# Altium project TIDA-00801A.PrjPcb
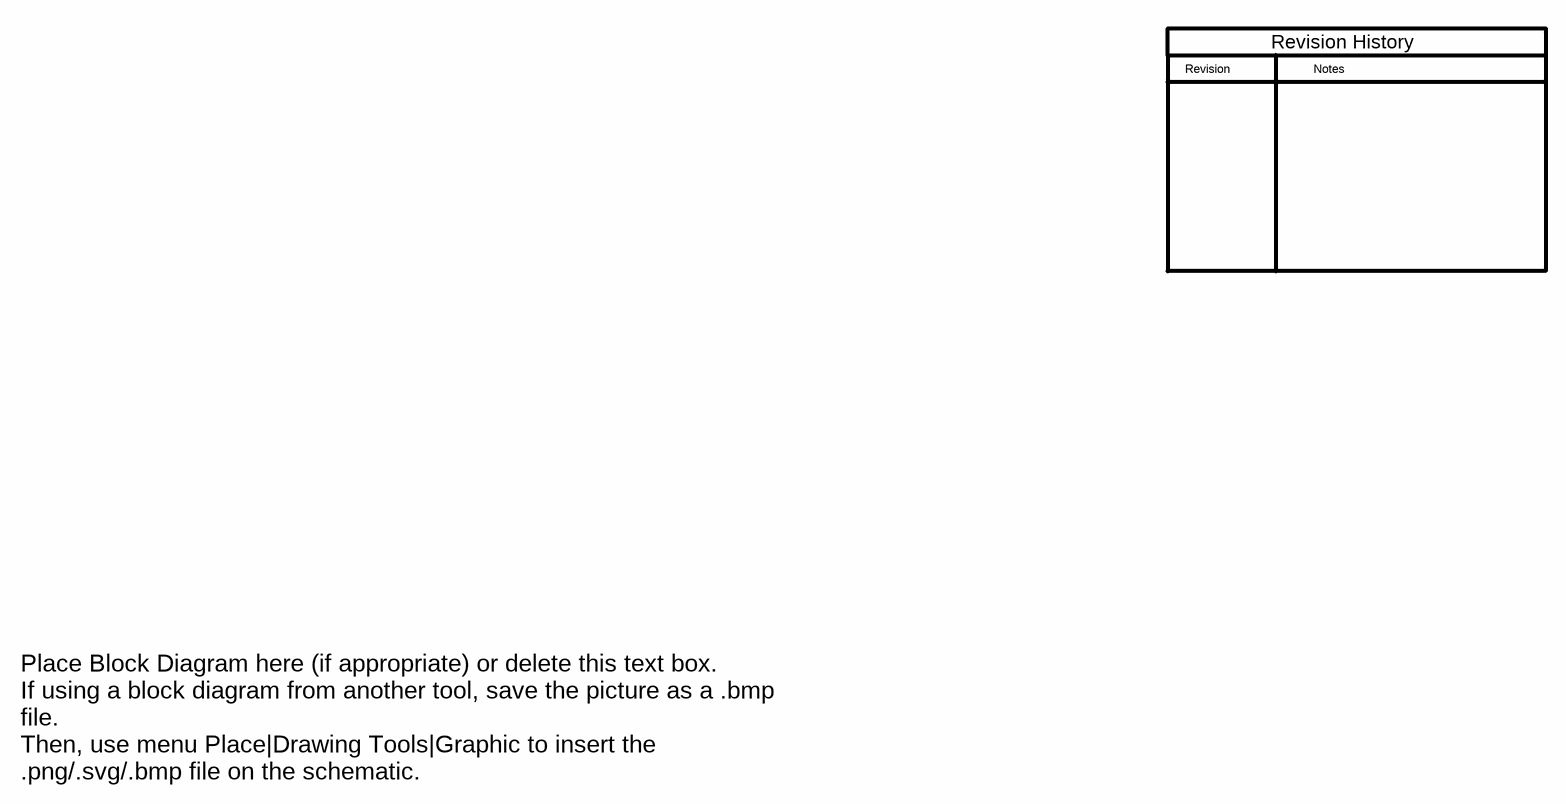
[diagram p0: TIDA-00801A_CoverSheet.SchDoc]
TID: TIDA-00801; TechSupport: http://www.ti.com/support; SCH_Rev: A; PRJ_Title: Infotainment-Power; PRJ_Number: TIDA-00801; PRJ_Engineer: Frank Dehmelt; PRJ_Customer: Public Release; PCB_Rev: A; PCB_Layout: Krypton Solutions/RS; CopyrightYear: 2015
6 sheets, 198 parts. Net scope: global (net labels, ports and power ports of the same name join across sheets).
Board file: TIDA-00801A.PcbDoc
Sheets:
  TIDA-00801A_CoverSheet.SchDoc
  TIDA-00801A_O9039A360.schdoc
  TIDA-00801A_TPS22965.schdoc
  TIDA-00801A_TPS43330.schdoc
  TIDA-00801A_TPS51200.schdoc
  TIDA-00801A_Hardware.SchDoc

## Sheet TIDA-00801A_CoverSheet.SchDoc
size 431 x 279 mm; Date: Not shown in title block; ApprovedBy: Not shown in title block; CheckedBy: Not shown in title block; Author: Not shown in title block; CompanyName: Not shown in title block; Engineer: Not shown in title block; Organization: Not shown in title block; Address1: Not shown in title block; Address2: Not shown in title block; Address3: Not shown in title block; Address4: Not shown in title block; DocumentNumber: 1; Revision: Use project parameter SCH_Rev; SheetNumber: 1; SheetTotal: 6; PageSetup: Record=PageOptions¦CenterHorizontal=True¦CenterVertical=True¦PrintScale=1.00¦XCorrection=1.00¦YCorrection=1.00¦PrintKind=0¦BorderSize=5000000¦LeftOffset=0¦BottomOffset=0¦Orientation=2¦PaperLength=1000¦PaperWidth=1000¦Scale=100¦PaperSource=15¦PrintQuality=600¦MediaType=1¦DitherType=10¦PaperKind=Letter¦PrintScaleMode=1

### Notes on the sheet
- Revision
- Notes
- Revision History
- Place Block Diagram here (if appropriate) or delete this text box.
  If using a block diagram from another tool, save the picture as a .bmp file.
  Then, use menu Place|Drawing Tools|Graphic to insert the .png/.svg/.bmp file on the schematic.

## Sheet TIDA-00801A_O9039A360.schdoc: O9039A360
size 558 x 431 mm; Date: Not shown in title block; ApprovedBy: Not shown in title block; CheckedBy: Not shown in title block; Author: Not shown in title block; CompanyName: Not shown in title block; Engineer: Not shown in title block; Organization: Not shown in title block; Address1: Not shown in title block; Address2: Not shown in title block; Address3: Not shown in title block; Address4: Not shown in title block; DocumentNumber: 1; Revision: Use project parameter SCH_Rev; SheetNumber: 5; SheetTotal: 6; PageSetup: Record=PageOptions¦CenterHorizontal=True¦CenterVertical=True¦PrintScale=0.54¦XCorrection=1.00¦YCorrection=1.00¦PrintKind=1¦BorderSize=5000000¦LeftOffset=0¦BottomOffset=0¦Orientation=2¦PaperLength=1000¦PaperWidth=1000¦Scale=100¦PaperSource=7¦PrintQuality=-3¦MediaType=1¦DitherType=10¦PrintScaleMode=1¦PaperKind=11x17¦PaperIndex=17
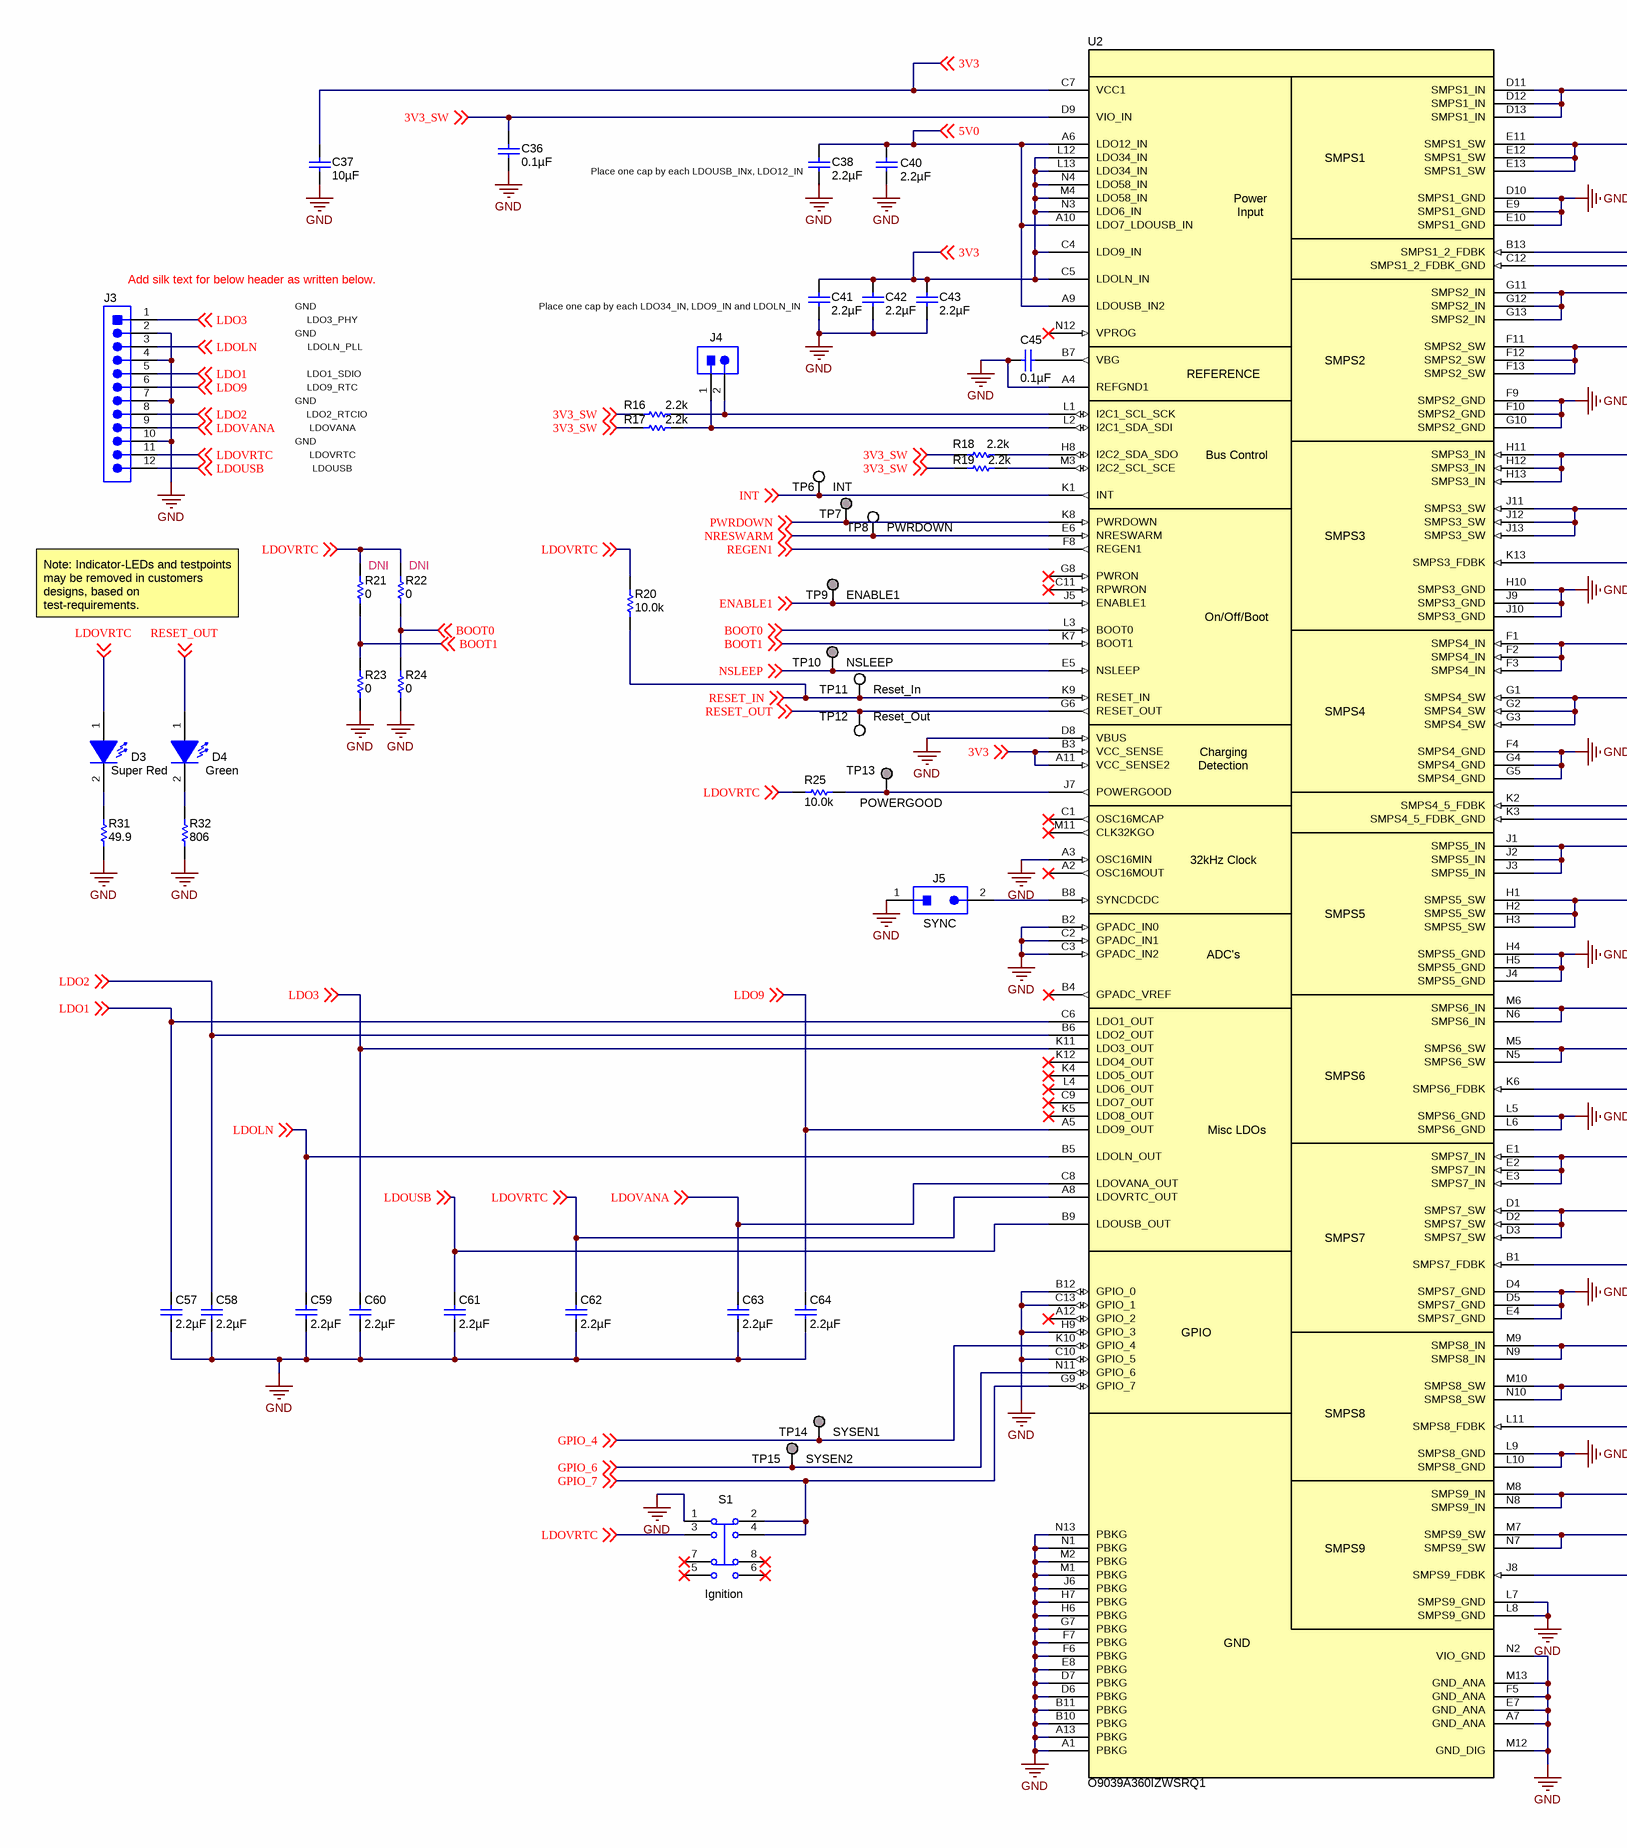
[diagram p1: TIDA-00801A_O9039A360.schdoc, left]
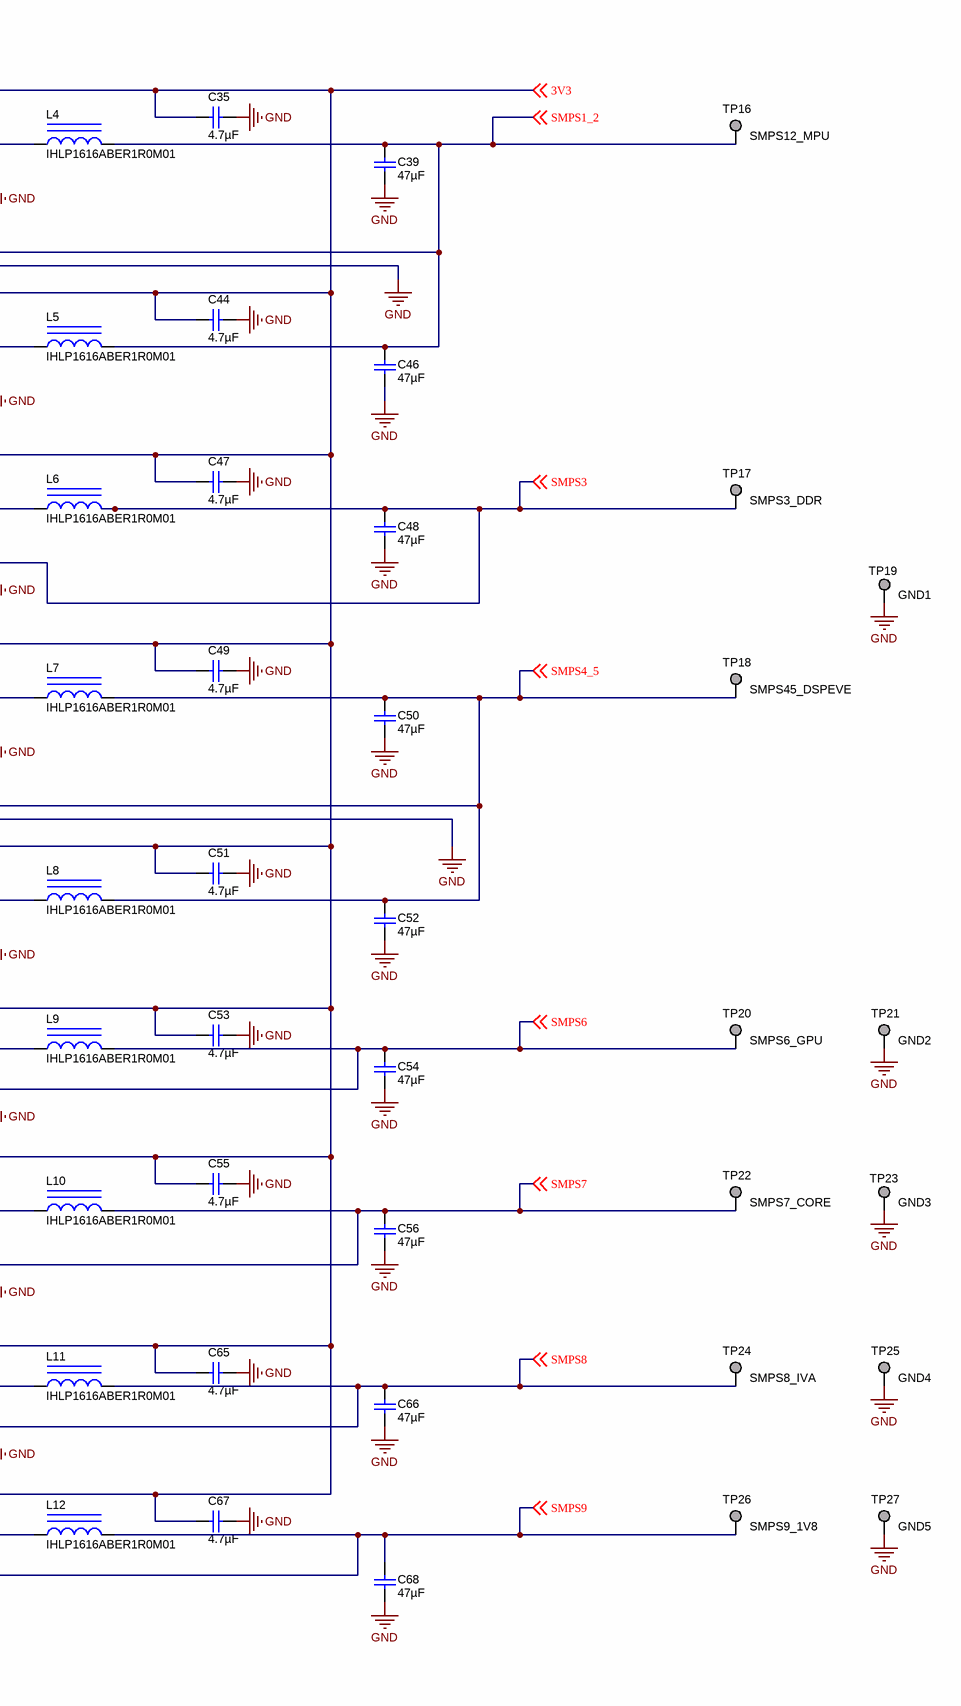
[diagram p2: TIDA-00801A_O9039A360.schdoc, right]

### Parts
C35  ValueDisplayed: 4.7µF  [0805L]  (hidden comment: C2012X5R1E475K125AB)
C36  ValueDisplayed: 0.1µF  [0402S]  (hidden comment: GCM155R71C104KA55D)
C37  ValueDisplayed: 10µF  [0603S]  (hidden comment: EMK107BBJ106MA-T)
C38  ValueDisplayed: 2.2µF  [0603]  (hidden comment: GRM188R61C225KAAD)
C39  ValueDisplayed: 47µF  [1210]  (hidden comment: GRM32ER71A476KE15L)
C40  ValueDisplayed: 2.2µF  [0603]  (hidden comment: GRM188R61C225KAAD)
C41  ValueDisplayed: 2.2µF  [0603L]  (hidden comment: GRM188R61C225KAAD)
C42  ValueDisplayed: 2.2µF  [0603L]  (hidden comment: GRM188R61C225KAAD)
C43  ValueDisplayed: 2.2µF  [0603L]  (hidden comment: GRM188R61C225KAAD)
C44  ValueDisplayed: 4.7µF  [0805L]  (hidden comment: C2012X5R1E475K125AB)
C45  ValueDisplayed: 0.1µF  [0402]  (hidden comment: GCM155R71C104KA55D)
C46  ValueDisplayed: 47µF  [1210]  (hidden comment: GRM32ER71A476KE15L)
C47  ValueDisplayed: 4.7µF  [0805L]  (hidden comment: C2012X5R1E475K125AB)
C48  ValueDisplayed: 47µF  [1210]  (hidden comment: GRM32ER71A476KE15L)
C49  ValueDisplayed: 4.7µF  [0805L]  (hidden comment: C2012X5R1E475K125AB)
C50  ValueDisplayed: 47µF  [1210]  (hidden comment: GRM32ER71A476KE15L)
C51  ValueDisplayed: 4.7µF  [0805L]  (hidden comment: C2012X5R1E475K125AB)
C52  ValueDisplayed: 47µF  [1210]  (hidden comment: GRM32ER71A476KE15L)
C53  ValueDisplayed: 4.7µF  [0805L]  (hidden comment: C2012X5R1E475K125AB)
C54  ValueDisplayed: 47µF  [1210]  (hidden comment: GRM32ER71A476KE15L)
C55  ValueDisplayed: 4.7µF  [0805L]  (hidden comment: C2012X5R1E475K125AB)
C56  ValueDisplayed: 47µF  [1210]  (hidden comment: GRM32ER71A476KE15L)
C57  ValueDisplayed: 2.2µF  [0402]  (hidden comment: GRM155R60J225ME15D)
C58  ValueDisplayed: 2.2µF  [0402]  (hidden comment: GRM155R60J225ME15D)
C59  ValueDisplayed: 2.2µF  [0402]  (hidden comment: GRM155R60J225ME15D)
C60  ValueDisplayed: 2.2µF  [0402]  (hidden comment: GRM155R60J225ME15D)
C61  ValueDisplayed: 2.2µF  [0402]  (hidden comment: GRM155R60J225ME15D)
C62  ValueDisplayed: 2.2µF  [0402]  (hidden comment: GRM155R60J225ME15D)
C63  ValueDisplayed: 2.2µF  [0402]  (hidden comment: GRM155R60J225ME15D)
C64  ValueDisplayed: 2.2µF  [0402]  (hidden comment: GRM155R60J225ME15D)
C65  ValueDisplayed: 4.7µF  [0805L]  (hidden comment: C2012X5R1E475K125AB)
C66  ValueDisplayed: 47µF  [1210]  (hidden comment: GRM32ER71A476KE15L)
C67  ValueDisplayed: 4.7µF  [0805L]  (hidden comment: C2012X5R1E475K125AB)
C68  ValueDisplayed: 47µF  [1210]  (hidden comment: GRM32ER71A476KE15L)
D3  value Super Red  [SML-LX0603SRW_SuperRed]  (hidden comment: SML-LX0603SRW-TR)
D4  value Green  [LG L29K_GREEN]  (hidden comment: LG L29K-G2J1-24-Z)
J3  TSW-112-07-G-S  [TSW-112-07-G-S]  (value not drawn)
J4  HTSW-102-07-G-S  [Samtec_HTSW-102-07-G-S]  (value not drawn)
J5  SYNC  [Samtec_HTSW-102-07-G-S]
L4  IHLP1616ABER1R0M01  [IHLP-1616AB]
L5  IHLP1616ABER1R0M01  [IHLP-1616AB]
L6  IHLP1616ABER1R0M01  [IHLP-1616AB]
L7  IHLP1616ABER1R0M01  [IHLP-1616AB]
L8  IHLP1616ABER1R0M01  [IHLP-1616AB]
L9  IHLP1616ABER1R0M01  [IHLP-1616AB]
L10  IHLP1616ABER1R0M01  [IHLP-1616AB]
L11  IHLP1616ABER1R0M01  [IHLP-1616AB]
L12  IHLP1616ABER1R0M01  [IHLP-1616AB]
R16  ValueDisplayed: 2.2k  [0402]  (hidden comment: CRCW04022K20JNED)
R17  ValueDisplayed: 2.2k  [0402]  (hidden comment: CRCW04022K20JNED)
R18  ValueDisplayed: 2.2k  [0402]  (hidden comment: CRCW04022K20JNED)
R19  ValueDisplayed: 2.2k  [0402]  (hidden comment: CRCW04022K20JNED)
R20  ValueDisplayed: 10.0k  [0603]  (hidden comment: RC0603FR-0710KL)
R21  ValueDisplayed: 0  [0402]  (hidden comment: RC0402JR-070RL)
R22  ValueDisplayed: 0  [0402]  (hidden comment: RC0402JR-070RL)
R23  ValueDisplayed: 0  [0402]  (hidden comment: RC0402JR-070RL)
R24  ValueDisplayed: 0  [0402]  (hidden comment: RC0402JR-070RL)
R25  ValueDisplayed: 10.0k  [0603]  (hidden comment: RC0603FR-0710KL)
R31  ValueDisplayed: 49.9  [0603]  (hidden comment: RC0603FR-0749R9L)
R32  ValueDisplayed: 806  [0603]  (hidden comment: CRCW0603806RFKEA)
S1  Ignition  [SW_15451]
TP6  INT  [Keystone5002]
TP7  PWRDOWN  [TP_H045P075]  (no BOM)
TP8  NRESWARM  [Keystone5002]  (value not drawn)
TP9  ENABLE1  [TP_H045P075]  (no BOM)
TP10  NSLEEP  [TP_H045P075]  (no BOM)
TP11  Reset_In  [Keystone5002]
TP12  Reset_Out  [Keystone5002]
TP13  POWERGOOD  [TP_H045P075]  (no BOM)
TP14  SYSEN1  [TP_H045P075]  (no BOM)
TP15  SYSEN2  [TP_H045P075]  (no BOM)
TP16  SMPS12_MPU  [Mill-Max_2505-2]
TP17  SMPS3_DDR  [Mill-Max_2505-2]
TP18  SMPS45_DSPEVE  [Mill-Max_2505-2]
TP19  GND1  [Mill-Max_2505-2]
TP20  SMPS6_GPU  [Mill-Max_2505-2]
TP21  GND2  [Mill-Max_2505-2]
TP22  SMPS7_CORE  [Mill-Max_2505-2]
TP23  GND3  [Mill-Max_2505-2]
TP24  SMPS8_IVA  [Mill-Max_2505-2]
TP25  GND4  [Mill-Max_2505-2]
TP26  SMPS9_1V8  [Mill-Max_2505-2]
TP27  GND5  [Mill-Max_2505-2]
U2  O9039A360IZWSRQ1  [ZWS0169A]

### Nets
GND: C35.1 C36.1 C37.2 C38.1 C39.2 C40.2 C41.2 C42.2 C43.2 C44.1 C45.2 C46.2 C47.1 C48.2 C49.1 C50.2 C51.1 C52.2 C53.1 C54.1 C55.1 C56.2 C57.2 C58.2 C59.2 C60.2 C61.2 C62.2 C63.2 C64.2 C65.1 C66.1 C67.1 C68.1 J3.2 J3.4 J3.7 J3.10 J5.1 R23.1 R24.1 R31.1 R32.1 S1.1 TP19.1 TP21.1 TP23.1 TP25.1 TP27.1 U2.A1(PBKG) U2.A3(OSC16MIN) U2.A4(REFGND1) U2.A7(GND_ANA) U2.A13(PBKG) U2.B2(GPADC_IN0) U2.B10(PBKG) U2.B11(PBKG) U2.B12(GPIO_0) U2.C2(GPADC_IN1) U2.C3(GPADC_IN2) U2.C10(GPIO_5) U2.C12(SMPS1_2_FDBK_GND) U2.C13(GPIO_1) U2.D4(SMPS7_GND) U2.D5(SMPS7_GND) U2.D6(PBKG) U2.D7(PBKG) U2.D8(VBUS) U2.D10(SMPS1_GND) U2.E4(SMPS7_GND) U2.E7(GND_ANA) U2.E8(PBKG) U2.E9(SMPS1_GND) U2.E10(SMPS1_GND) U2.F4(SMPS4_GND) U2.F5(GND_ANA) U2.F6(PBKG) U2.F7(PBKG) U2.F9(SMPS2_GND) U2.F10(SMPS2_GND) U2.G4(SMPS4_GND) U2.G5(SMPS4_GND) U2.G7(PBKG) U2.G10(SMPS2_GND) U2.H4(SMPS5_GND) U2.H5(SMPS5_GND) U2.H6(PBKG) U2.H7(PBKG) U2.H9(GPIO_3) U2.H10(SMPS3_GND) U2.J4(SMPS5_GND) U2.J6(PBKG) U2.J9(SMPS3_GND) U2.J10(SMPS3_GND) U2.K3(SMPS4_5_FDBK_GND) U2.L5(SMPS6_GND) U2.L6(SMPS6_GND) U2.L7(SMPS9_GND) U2.L8(SMPS9_GND) U2.L9(SMPS8_GND) U2.L10(SMPS8_GND) U2.M1(PBKG) U2.M2(PBKG) U2.M12(GND_DIG) U2.M13(GND_ANA) U2.N1(PBKG) U2.N2(VIO_GND) U2.N13(PBKG)
3V3: C35.2 C37.1 C41.1 C42.1 C43.1 C44.2 C47.2 C49.2 C51.2 C53.2 C55.2 C65.2 C67.2 U2.A11(VCC_SENSE2) U2.B3(VCC_SENSE) U2.C4(LDO9_IN) U2.C5(LDOLN_IN) U2.C7(VCC1) U2.D11(SMPS1_IN) U2.D12(SMPS1_IN) U2.D13(SMPS1_IN) U2.E1(SMPS7_IN) U2.E2(SMPS7_IN) U2.E3(SMPS7_IN) U2.F1(SMPS4_IN) U2.F2(SMPS4_IN) U2.F3(SMPS4_IN) U2.G11(SMPS2_IN) U2.G12(SMPS2_IN) U2.G13(SMPS2_IN) U2.H11(SMPS3_IN) U2.H12(SMPS3_IN) U2.H13(SMPS3_IN) U2.J1(SMPS5_IN) U2.J2(SMPS5_IN) U2.J3(SMPS5_IN) U2.L12(LDO34_IN) U2.L13(LDO34_IN) U2.M4(LDO58_IN) U2.M6(SMPS6_IN) U2.M8(SMPS9_IN) U2.M9(SMPS8_IN) U2.N3(LDO6_IN) U2.N4(LDO58_IN) U2.N6(SMPS6_IN) U2.N8(SMPS9_IN) U2.N9(SMPS8_IN) ; off-sheet 3V3
3V3_SW: C36.2 R16.2 R17.2 R18.2 R19.2 U2.D9(VIO_IN) ; off-sheet 3V3_SW
5V0: C38.2 C40.1 U2.A6(LDO12_IN) U2.A9(LDOUSB_IN2) U2.A10(LDO7_LDOUSB_IN) ; off-sheet 5V0
BOOT0: R22.1 R24.2 U2.L3(BOOT0) ; off-sheet BOOT0
BOOT1: R21.1 R23.2 U2.K7(BOOT1) ; off-sheet BOOT1
ENABLE1: TP9.1 U2.J5(ENABLE1) ; off-sheet ENABLE1
GPIO_4: TP14.1 U2.K10(GPIO_4) ; off-sheet GPIO_4
GPIO_6: TP15.1 U2.N11(GPIO_6) ; off-sheet GPIO_6
GPIO_7: S1.2 S1.4 U2.G9(GPIO_7) ; off-sheet GPIO_7
INT: TP6.1 U2.K1(INT) ; off-sheet INT
LDO1: C57.1 J3.5 U2.C6(LDO1_OUT) ; off-sheet LDO1
LDO2: C58.1 J3.8 U2.B6(LDO2_OUT) ; off-sheet LDO2
LDO3: C60.1 J3.1 U2.K11(LDO3_OUT) ; off-sheet LDO3
LDO9: C64.1 J3.6 U2.A5(LDO9_OUT) ; off-sheet LDO9
LDOLN: C59.1 J3.3 U2.B5(LDOLN_OUT) ; off-sheet LDOLN
LDOUSB: C61.1 J3.12 U2.B9(LDOUSB_OUT) ; off-sheet LDOUSB
LDOVANA: C63.1 J3.9 U2.C8(LDOVANA_OUT) ; off-sheet LDOVANA
LDOVRTC: C62.1 D3.1(A) J3.11 R20.1 R21.2 R22.2 R25.2 S1.3 U2.A8(LDOVRTC_OUT) ; off-sheet LDOVRTC
NRESWARM: TP8.1 U2.E6(NRESWARM) ; off-sheet NRESWARM
NSLEEP: TP10.1 U2.E5(NSLEEP) ; off-sheet NSLEEP
PWRDOWN: TP7.1 U2.K8(PWRDOWN) ; off-sheet PWRDOWN
REGEN1: U2.F8(REGEN1) ; off-sheet REGEN1
RESET_IN: R20.2 TP11.1 U2.K9(RESET_IN) ; off-sheet RESET_IN
RESET_OUT: D4.1(A) TP12.1 U2.G6(RESET_OUT) ; off-sheet RESET_OUT
SMPS1_2: C39.1 C46.1 L4.2 L5.2 TP16.1 U2.B13(SMPS1_2_FDBK) ; off-sheet SMPS1_2
SMPS3: C48.1 L6.2 TP17.1 U2.K13(SMPS3_FDBK) ; off-sheet SMPS3
SMPS4_5: C50.1 C52.1 L7.2 L8.2 TP18.1 U2.K2(SMPS4_5_FDBK) ; off-sheet SMPS4_5
SMPS6: C54.2 L9.2 TP20.1 U2.K6(SMPS6_FDBK) ; off-sheet SMPS6
SMPS7: C56.1 L10.2 TP22.1 U2.B1(SMPS7_FDBK) ; off-sheet SMPS7
SMPS8: C66.2 L11.2 TP24.1 U2.L11(SMPS8_FDBK) ; off-sheet SMPS8
SMPS9: C68.2 L12.2 TP26.1 U2.J8(SMPS9_FDBK) ; off-sheet SMPS9
NetC45_1: C45.1 U2.B7(VBG)
NetD3_2: D3.2(K) R31.2
NetD4_2: D4.2(K) R32.2
NetJ4_1: J4.1 R17.1 U2.L2(I2C1_SDA_SDI)
NetJ4_2: J4.2 R16.1 U2.L1(I2C1_SCL_SCK)
NetJ5_2: J5.2 U2.B8(SYNCDCDC)
NetL4_1: L4.1 U2.E11(SMPS1_SW) U2.E12(SMPS1_SW) U2.E13(SMPS1_SW)
NetL5_1: L5.1 U2.F11(SMPS2_SW) U2.F12(SMPS2_SW) U2.F13(SMPS2_SW)
NetL6_1: L6.1 U2.J11(SMPS3_SW) U2.J12(SMPS3_SW) U2.J13(SMPS3_SW)
NetL7_1: L7.1 U2.G1(SMPS4_SW) U2.G2(SMPS4_SW) U2.G3(SMPS4_SW)
NetL8_1: L8.1 U2.H1(SMPS5_SW) U2.H2(SMPS5_SW) U2.H3(SMPS5_SW)
NetL9_1: L9.1 U2.M5(SMPS6_SW) U2.N5(SMPS6_SW)
NetL10_1: L10.1 U2.D1(SMPS7_SW) U2.D2(SMPS7_SW) U2.D3(SMPS7_SW)
NetL11_1: L11.1 U2.M10(SMPS8_SW) U2.N10(SMPS8_SW)
NetL12_1: L12.1 U2.M7(SMPS9_SW) U2.N7(SMPS9_SW)
NetR18_1: R18.1 U2.H8(I2C2_SDA_SDO)
NetR19_1: R19.1 U2.M3(I2C2_SCL_SCE)
NetR25_1: R25.1 TP13.1 U2.J7(POWERGOOD)

Not connected (* = marked no-connect by the designer): S1 5* 6* 7* 8*; U2 A2(OSC16MOUT)* A12(GPIO_2)* B4(GPADC_VREF)* C1(OSC16MCAP)* C9(LDO7_OUT)* C11(RPWRON)* G8(PWRON)* K4(LDO5_OUT)* K5(LDO8_OUT)* K12(LDO4_OUT)* L4(LDO6_OUT)* M11(CLK32KGO)* N12(VPROG)*

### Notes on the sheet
- (near C38) Place one cap by each LDOUSB_INx, LDO12_IN
- (near J3) Add silk text for below header as written below.
- GND
- LDO3_PHY
- (near C41) Place one cap by each LDO34_IN, LDO9_IN and LDOLN_IN
- LDO9_RTC
- LDO1_SDIO
- LDOLN_PLL
- LDOVRTC
- LDOVANA
- LDO2_RTCIO
- LDOUSB
- DNI
- (near R22) DNI
- Note: Indicator-LEDs and testpoints may be removed in customers designs, based on test-requirements.

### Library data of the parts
C35 C44 C47 C49 C51 C53 C55 C65 C67 = C2012X5R1E475K125AB: CAP, CERM, 4.7 µF, 25 V, +/- 10%, X5R, 0805; Manufacturer: TDK; Polarized: N; CompType: Capacitor; Value: 4.7uF; U/M: EA; Cap_F: 0.0000047; Tolerance_%: 10; Value1: Unknown; VDC_V: 25; Value2: 25V; TaMin_C: -55; TaMax_C: 85; Cap_Case: 0805
C36 = GCM155R71C104KA55D: CAP, CERM, 0.1 µF, 16 V, +/- 10%, X7R, 0402; Manufacturer: MuRata; Polarized: N; CompType: Capacitor; Value: 0.1uF; U/M: EA; Cap_F: 0.0000001; Tolerance_%: 10; Value1: Unknown; VDC_V: 16; Value2: 16V; TaMin_C: -55; TaMax_C: 125; Cap_Case: 0402
C37 = EMK107BBJ106MA-T: CAP, CERM, 10 µF, 16 V, +/- 20%, X5R, 0603; Manufacturer: Taiyo Yuden; Polarized: N; CompType: Capacitor; Value: 10uF; U/M: EA; Cap_F: 0.00001; Tolerance_%: 20; Value1: Unknown; VDC_V: 16; Value2: 16V; TaMin_C: -55; TaMax_C: 85; Cap_Case: 0603
C38 C40 = GRM188R61C225KAAD: CAP, CERM, 2.2 µF, 16 V, +/- 10%, X5R, 0603; Manufacturer: MuRata; Polarized: N; CompType: Capacitor; Value: 2.2uF; U/M: EA; Cap_F: 0.0000022; Tolerance_%: 10; Value1: Unknown; VDC_V: 16; Value2: 16V; TaMin_C: -55; TaMax_C: 85
C39 C46 C48 C50 C52 C54 C56 C66 C68 = GRM32ER71A476KE15L: CAP, CERM, 47 µF, 10 V, +/- 10%, X7R, 1210; Manufacturer: MuRata; Polarized: N; CompType: Capacitor; Value: 47uF; U/M: EA; Cap_F: 0.000047; Tolerance_%: 10; Value1: Unknown; Value2: 10V; TaMin_C: -55; TaMax_C: 125
C41-C43 = GRM188R61C225KAAD: CAP, CERM, 2.2 µF, 16 V, +/- 10%, X5R, 0603; Manufacturer: MuRata; Polarized: N; CompType: Capacitor; Value: 2.2uF; U/M: EA; Cap_F: 0.0000022; Tolerance_%: 10; Value1: Unknown; VDC_V: 16; Value2: 16V; TaMin_C: -55; TaMax_C: 85; Cap_Case: 0603
C45 = GCM155R71C104KA55D: CAP, CERM, 0.1 µF, 16 V, +/- 10%, X7R, 0402; Manufacturer: MuRata; Polarized: N; CompType: Capacitor; Value: 0.1uF; U/M: EA; Cap_F: 0.0000001; Tolerance_%: 10; Value1: Unknown; VDC_V: 16; Value2: 16V; TaMin_C: -55; TaMax_C: 125
C57-C64 = GRM155R60J225ME15D: CAP, CERM, 2.2 µF, 6.3 V, +/- 20%, X5R, 0402; Manufacturer: MuRata; Polarized: N; CompType: Capacitor; Value: 2.2uF; U/M: EA; Cap_F: 0.0000022; Tolerance_%: 20; ESR_ohm: 0.005; Value1: 0.005 ohm; VDC_V: 6.3; Value2: 6.3V; IRMS_A: 3.67; TaMin_C: -55; TaMax_C: 125
D3 = SML-LX0603SRW-TR: LED, Super Red, SMD; Manufacturer: Lumex; Vf_V: 1.7; Value2: 1.7V; Io_A: 0.02; Value1: W; U/M: EA
D4 = LG L29K-G2J1-24-Z: LED, Green, SMD; Manufacturer: OSRAM; Vf_V: 1.7; Value2: 1.7V; Io_A: 0.002; Tjmax_C: 110; Value1: W; U/M: EA
J3 = TSW-112-07-G-S: Header, 100mil, 12x1, Gold, TH; Manufacturer: Samtec; SymbolCreator: a0412235; U/M: EA
J4 J5 = HTSW-102-07-G-S: Header, 100mil, 2x1, Gold, TH; Manufacturer: Samtec; SymbolCreator: a0412235; U/M: EA
L4-L12 = IHLP1616ABER1R0M01: Inductor, Shielded Drum Core, Powdered Iron, 1 µH, 4 A, 0.05 ohm, SMD; Manufacturer: Vishay-Dale; Value: 1uH; Ind_H: 1.0E-6; ValueDisplayed: 1µH; Imax_A: 4; Irms: 4A @ 40C rise; Isat: 8.5A @ 20% inductance drop; DCR_ohm: 0.05; Value2: 4A
R16-R19 = CRCW04022K20JNED: RES, 2.2 k, 5%, 0.063 W, 0402; Manufacturer: Vishay-Dale; CompType: Resistor; Value: 2.2k; Res_ohm: 2200; Value_Code: 2k20; Tolerance_%: 5; Power_W: 0.063; Value2: 0.063W; VDC_V: 50; TempCo: 200 ppm/C; EIA_Code: E24; U/M: EA
R20 R25 = RC0603FR-0710KL: RES, 10.0 k, 1%, 0.1 W, 0603; Manufacturer: Yageo America; CompType: Resistor; Value: 10.0k; Res_ohm: 10000; Value_Code: 10k0; Tolerance_%: 1; Power_W: 0.1; Value2: 0.1W; VDC_V: 150; TempCo: 200 ppm/C; EIA_Code: E96; U/M: EA
R21-R24 = RC0402JR-070RL: RES, 0, 5%, 0.063 W, 0402; Manufacturer: Yageo America; CompType: Resistor; Value: 0; Value_Code: 0000; Tolerance_%: 5; Power_W: 0.063; Value2: 0.063W; VDC_V: 50; TempCo: 200 ppm/C; EIA_Code: E24; U/M: EA
R31 = RC0603FR-0749R9L: RES, 49.9, 1%, 0.1 W, 0603; Manufacturer: Yageo America; CompType: Resistor; Value: 49.9; Value_Code: 49R9; Tolerance_%: 1; Power_W: 0.1; Value2: 0.1W; VDC_V: 150; TempCo: 200 ppm/C; EIA_Code: E96; U/M: EA
R32 = CRCW0603806RFKEA: RES, 806, 1%, 0.1 W, 0603; Manufacturer: Vishay-Dale; CompType: Resistor; Value: 806; Value_Code: 806R; Tolerance_%: 1; Power_W: 0.1; Value2: 0.1W; VDC_V: 75; TempCo: 100 ppm/C; EIA_Code: E96; U/M: EA
S1 = 15451: Switch, 4PST, 0.25 A, 120 V, TH; Manufacturer: MEC Switches; SymbolCreator: Altium; SwitchFunction: Off-On; PositionCount: 2; CurrentRating_mA: 250
TP6 TP8 TP11 TP12 = 5002: Test Point, Miniature, White, TH; Manufacturer: Keystone; CompType: Test Point Loop; U/M: EA
TP7 TP9 TP10 TP13-TP15 = TP_H0.45P0.75: Testpoint; Manufacturer: Texas Instruments; CompType: Pad
TP16-TP27 = 2505-2-00-44-00-00-07-0: PCB Pin, Swage Mount, TH; Manufacturer: Mill-Max; CompType: PCB Pin
U2 = O9039A360IZWSRQ1: Automotive Power Management Unit (PMU) for Processor, ZWS0169A; Manufacturer: Texas Instruments; SymbolCreator: Altium; CompType: IC; U/M: EA

## Sheet TIDA-00801A_TPS22965.schdoc: TPS22965
size 431 x 279 mm; Date: Not shown in title block; ApprovedBy: Not shown in title block; CheckedBy: Not shown in title block; Author: Not shown in title block; CompanyName: Not shown in title block; Engineer: Not shown in title block; Organization: Not shown in title block; Address1: Not shown in title block; Address2: Not shown in title block; Address3: Not shown in title block; Address4: Not shown in title block; DocumentNumber: 1; Revision: Use project parameter SCH_Rev; SheetNumber: 2; SheetTotal: 6; PageSetup: Record=PageOptions¦CenterHorizontal=True¦CenterVertical=True¦PrintScale=1.00¦XCorrection=1.00¦YCorrection=1.00¦PrintKind=0¦BorderSize=5000000¦LeftOffset=0¦BottomOffset=0¦Orientation=2¦PaperLength=1000¦PaperWidth=1000¦Scale=100¦PaperSource=15¦PrintQuality=600¦MediaType=1¦DitherType=10¦PaperKind=Letter¦PrintScaleMode=1
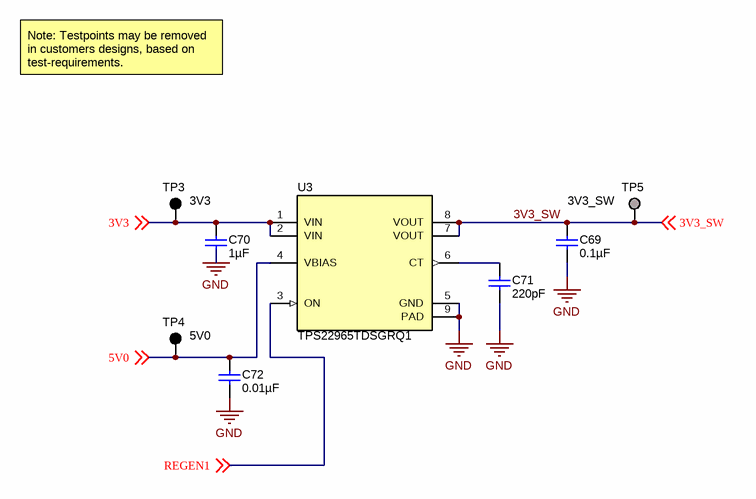
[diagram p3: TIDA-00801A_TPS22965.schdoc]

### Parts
C69  ValueDisplayed: 0.1µF  [0603]  (hidden comment: GRM188R61C104KA01D)
C70  ValueDisplayed: 1µF  [0603]  (hidden comment: GRM185R61C105KE44D)
C71  ValueDisplayed: 220pF  [0603]  (hidden comment: C1608X7R1H221K)
C72  ValueDisplayed: 0.01µF  [0402]  (hidden comment: GRM155R61A103KA01D)
TP3  3V3  [Keystone5006]
TP4  5V0  [Keystone5006]
TP5  3V3_SW  [Mill-Max_2505-2]
U3  TPS22965TDSGRQ1  [DSG0008A]

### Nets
GND: C69.2 C70.2 C71.2 C72.2 U3.5(GND) U3.9(PAD)
3V3: C70.1 TP3.1 U3.1(VIN) U3.2(VIN) ; off-sheet 3V3
3V3_SW: C69.1 TP5.1 U3.7(VOUT) U3.8(VOUT) ; off-sheet 3V3_SW
5V0: C72.1 TP4.1 U3.4(VBIAS) ; off-sheet 5V0
REGEN1: U3.3(ON) ; off-sheet REGEN1
NetC71_1: C71.1 U3.6(CT)

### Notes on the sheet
- Note: Testpoints may be removed in customers designs, based on test-requirements.

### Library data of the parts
C69 = GRM188R61C104KA01D: CAP, CERM, 0.1 µF, 16 V, +/- 10%, X5R, 0603; Manufacturer: MuRata; Polarized: N; CompType: Capacitor; Value: 0.1uF; U/M: EA; Cap_F: 0.0000001; Tolerance_%: 10; Value1: Unknown; VDC_V: 16; Value2: 16V; TaMin_C: -55; TaMax_C: 85
C70 = GRM185R61C105KE44D: CAP, CERM, 1 µF, 16 V, +/- 10%, X5R, 0603; Manufacturer: MuRata; Polarized: N; CompType: Capacitor; Value: 1uF; U/M: EA; Cap_F: 0.000001; Tolerance_%: 10; Value1: Unknown; VDC_V: 16; Value2: 16V; TaMin_C: -55; TaMax_C: 85
C71 = C1608X7R1H221K: CAP, CERM, 220 pF, 50 V, +/- 10%, X7R, 0603; Manufacturer: TDK; Polarized: N; CompType: Capacitor; Value: 220pF; U/M: EA; Cap_F: 0.00000000022; Tolerance_%: 10; Value1: Unknown; VDC_V: 50; Value2: 50V; TaMin_C: -55; TaMax_C: 125
C72 = GRM155R61A103KA01D: CAP, CERM, 0.01 µF, 10 V, +/- 10%, X5R, 0402; Manufacturer: MuRata; Polarized: N; CompType: Capacitor; Value: 0.01uF; U/M: EA; Cap_F: 0.00000001; Tolerance_%: 10; Value1: Unknown; Value2: 10V; TaMin_C: -55; TaMax_C: 85
TP3 TP4 = 5006: Test Point, Compact, Black, TH; Manufacturer: Keystone; CompType: Test Point Loop; U/M: EA
TP5 = 2505-2-00-44-00-00-07-0: as TP16 on sheet TIDA-00801A_O9039A360
U3 = TPS22965TDSGRQ1: 5.5-V, 4-A, 16-mΩ On-Resistance Load Switch, DSG0008A; Alternate PartNumber: TPS22965TDSGTQ1; Manufacturer: Texas Instruments; SymbolCreator: a0411947; CompType: IC; U/M: EA

## Sheet TIDA-00801A_TPS43330.schdoc: TPS43330
size 431 x 279 mm; Date: Not shown in title block; ApprovedBy: Not shown in title block; CheckedBy: Not shown in title block; Author: Not shown in title block; CompanyName: Not shown in title block; Engineer: Not shown in title block; Organization: Not shown in title block; Address1: Not shown in title block; Address2: Not shown in title block; Address3: Not shown in title block; Address4: Not shown in title block; DocumentNumber: 1; Revision: Use project parameter SCH_Rev; SheetNumber: 4; SheetTotal: 6; PageSetup: Record=PageOptions¦CenterHorizontal=True¦CenterVertical=True¦PrintScale=0.62¦XCorrection=1.00¦YCorrection=1.00¦PrintKind=0¦BorderSize=5000000¦LeftOffset=0¦BottomOffset=0¦Orientation=2¦PaperLength=1000¦PaperWidth=1000¦Scale=100¦PaperSource=15¦PrintQuality=600¦MediaType=1¦DitherType=10¦PrintScaleMode=1¦PaperKind=Letter
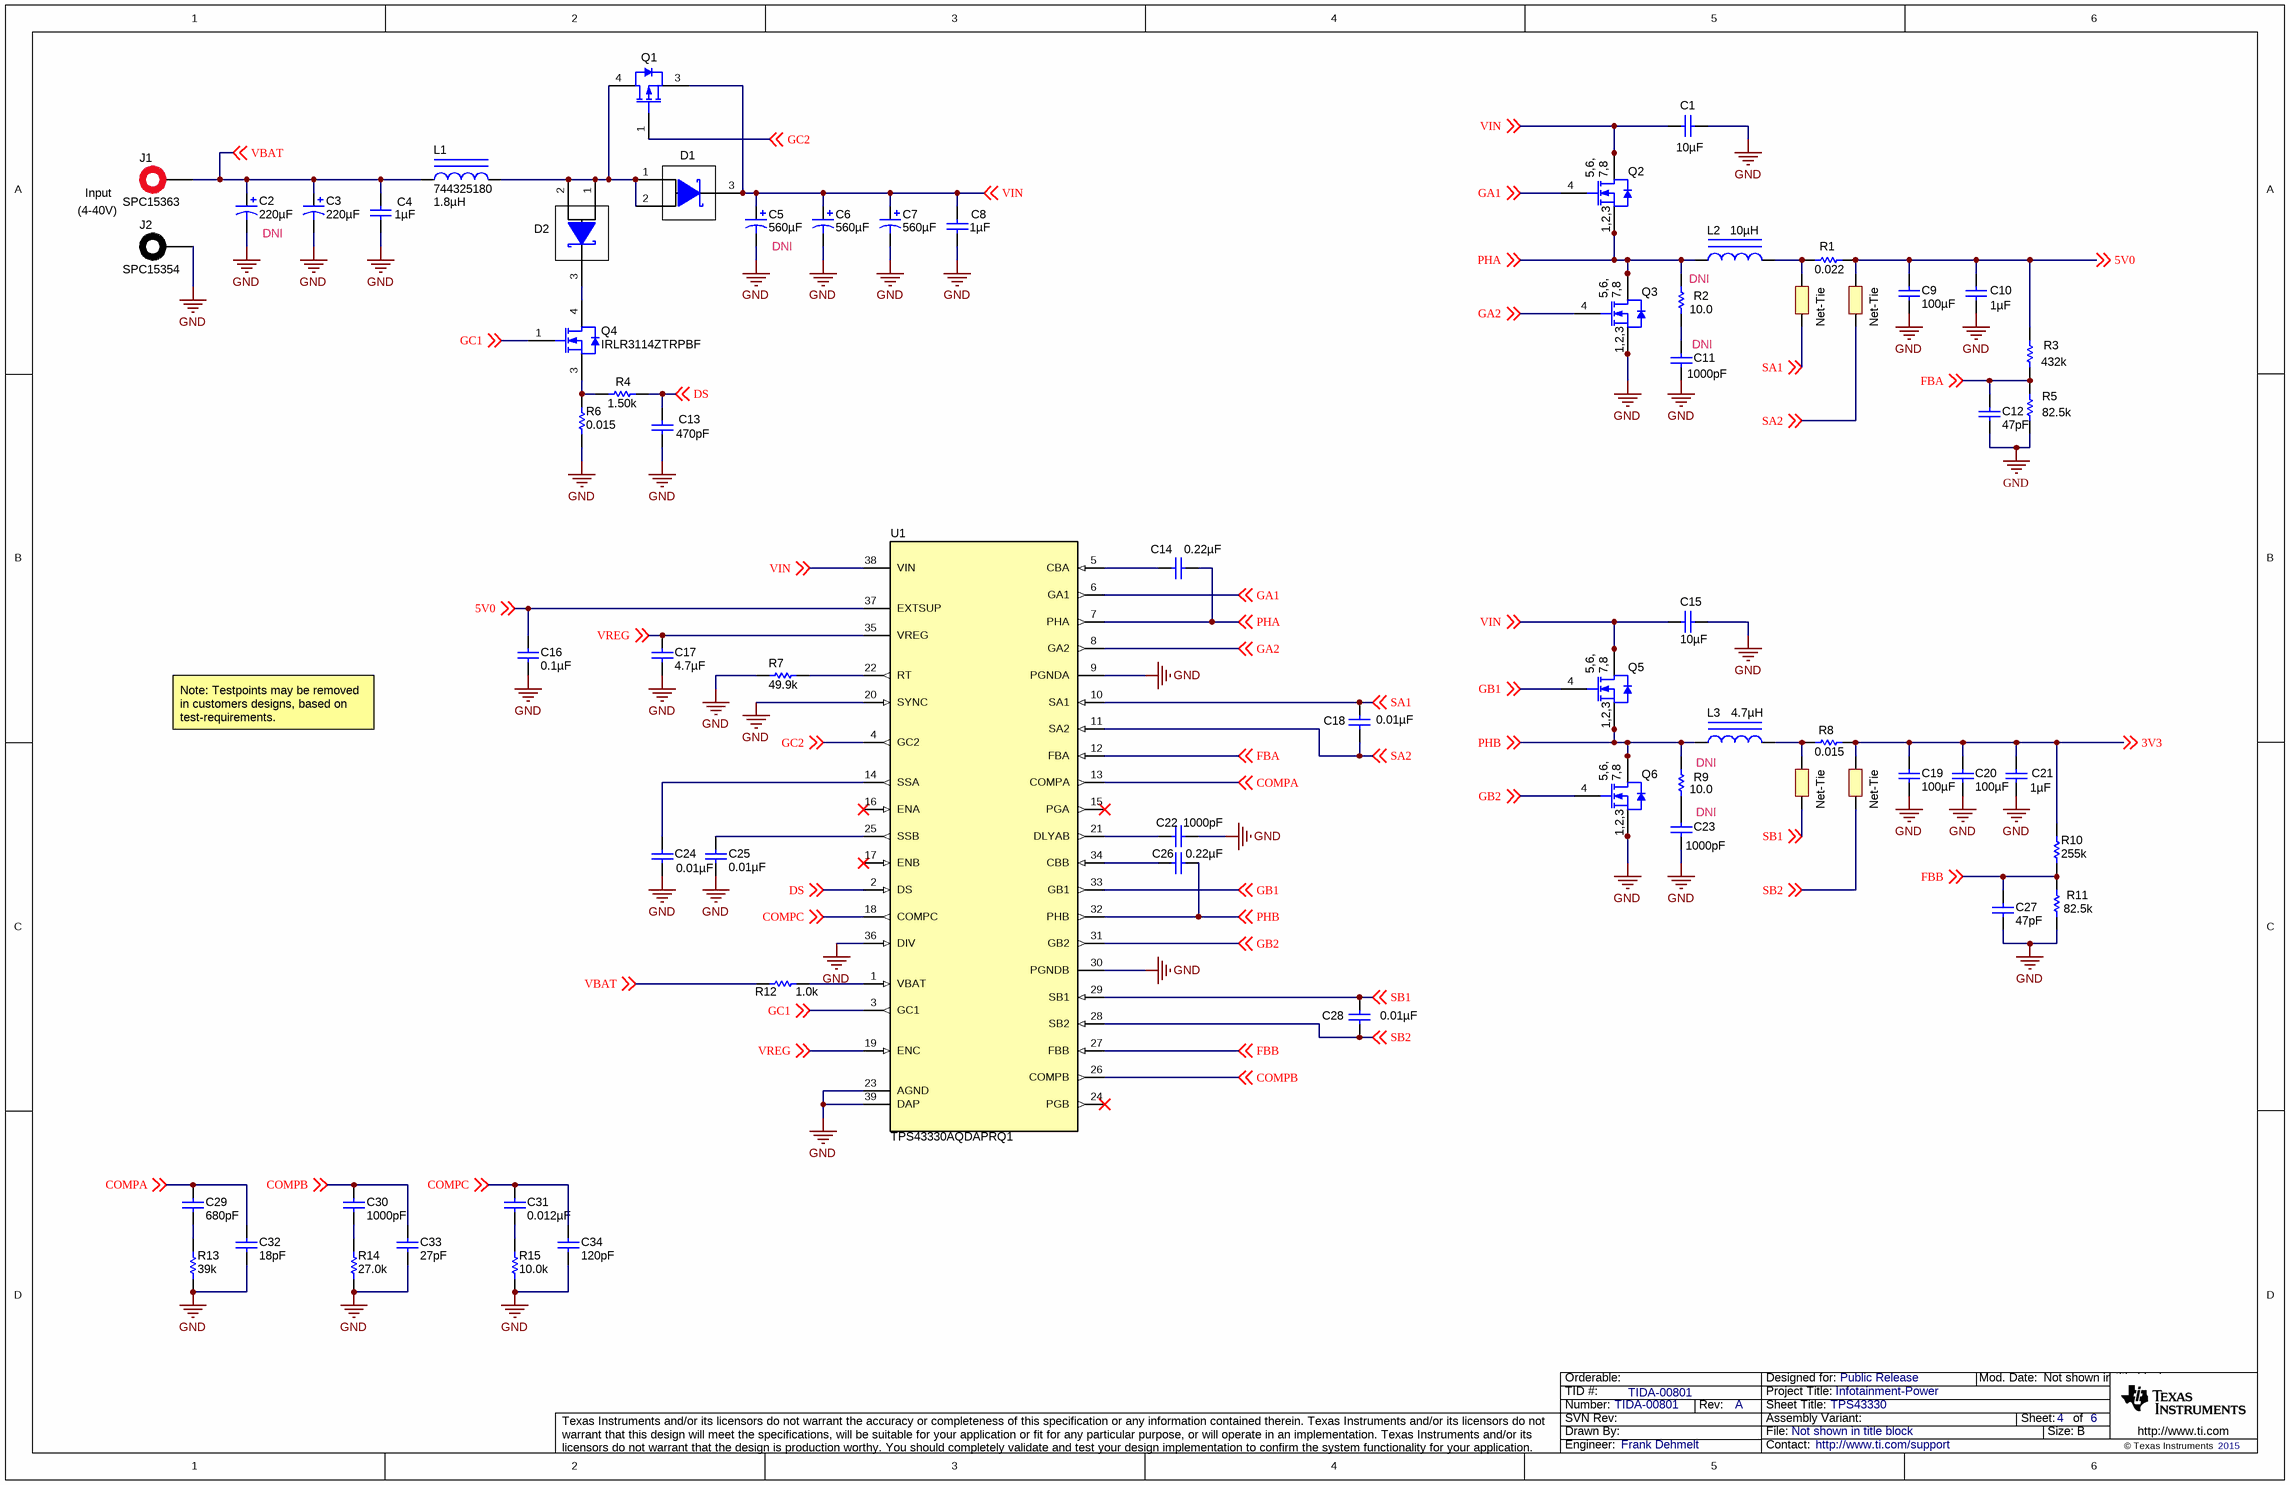
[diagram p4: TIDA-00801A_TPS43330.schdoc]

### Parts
C1  ValueDisplayed: 10µF  [2220]  (hidden comment: CGA9N3X7R1H106K230KB)
C2  ValueDisplayed: 220µF  [SM_RADIAL_H13]  (hidden comment: EEE-TK1J221AQ)
C3  ValueDisplayed: 220µF  [SM_RADIAL_H13]  (hidden comment: EEE-TK1J221AQ)
C4  ValueDisplayed: 1µF  [1206_190]  (hidden comment: CL31B105JAHNNNE)
C5  ValueDisplayed: 560µF  [FC_1250x2500]  (hidden comment: EEU-FC1H561)
C6  ValueDisplayed: 560µF  [FC_1250x2500]  (hidden comment: EEU-FC1H561)
C7  ValueDisplayed: 560µF  [FC_1250x2500]  (hidden comment: EEU-FC1H561)
C8  ValueDisplayed: 1µF  [1206_190]  (hidden comment: CL31B105JAHNNNE)
C9  ValueDisplayed: 100µF  [1210_280]  (hidden comment: LMK325ABJ107MMHT)
C10  ValueDisplayed: 1µF  [1206]  (hidden comment: C1206C105K3RACTU)
C11  ValueDisplayed: 1000pF  [0603]  (hidden comment: GRM1885C1E102JA01D)
C12  ValueDisplayed: 47pF  [0603]  (hidden comment: GRM1885C1H470JA01D)
C13  ValueDisplayed: 470pF  [0603]  (hidden comment: C0603C471K5RACTU)
C14  ValueDisplayed: 0.22µF  [0603_HV]  (hidden comment: GRM188R61E224KA88D)
C15  ValueDisplayed: 10µF  [2220]  (hidden comment: CGA9N3X7R1H106K230KB)
C16  ValueDisplayed: 0.1µF  [0603]  (hidden comment: C0603C104J3RACTU)
C17  ValueDisplayed: 4.7µF  [0603_095]  (hidden comment: GRM188R61E475KE11D)
C18  ValueDisplayed: 0.01µF  [0603]  (hidden comment: GRM188R71E103KA01D)
C19  ValueDisplayed: 100µF  [1210_280]  (hidden comment: LMK325ABJ107MMHT)
C20  ValueDisplayed: 100µF  [1210_280]  (hidden comment: LMK325ABJ107MMHT)
C21  ValueDisplayed: 1µF  [1206]  (hidden comment: C1206C105K3RACTU)
C22  ValueDisplayed: 1000pF  [0603]  (hidden comment: GRM188R71H102KA01D)
C23  ValueDisplayed: 1000pF  [0603]  (hidden comment: GRM188R71H102KA01D)
C24  ValueDisplayed: 0.01µF  [0603]  (hidden comment: GRM188R71E103KA01D)
C25  ValueDisplayed: 0.01µF  [0603]  (hidden comment: GRM188R71E103KA01D)
C26  ValueDisplayed: 0.22µF  [0603_HV]  (hidden comment: GRM188R61E224KA88D)
C27  ValueDisplayed: 47pF  [0603]  (hidden comment: GRM1885C1H470JA01D)
C28  ValueDisplayed: 0.01µF  [0603]  (hidden comment: GRM188R71E103KA01D)
C29  ValueDisplayed: 680pF  [0402]  (hidden comment: C1005C0G1E681J)
C30  ValueDisplayed: 1000pF  [0603]  (hidden comment: C0603X102K5RACTU)
C31  ValueDisplayed: 0.012µF  [0603]  (hidden comment: 06033C123JAT2A)
C32  ValueDisplayed: 18pF  [0603]  (hidden comment: C1608C0G1H180J)
C33  ValueDisplayed: 27pF  [0603]  (hidden comment: 06035A270JAT2A)
C34  ValueDisplayed: 120pF  [0603]  (hidden comment: GRM1885C1H121JA01D)
D1  PMEG045V150EPDAZ  [SOT1289]  (value not drawn)
D2  PMEG045V150EPDAZ  [SOT1289]  (value not drawn)
J1  SPC15363  [Tenma_SPC15363]
J2  SPC15354  [Tenma_SPC15354]
L1  744325180  ValueDisplayed: 1.8µH  [WE-HC6]
L2  ValueDisplayed: 10µH  [IHLP-2525CZ]  (hidden comment: IHLP2525CZER100M01)
L3  ValueDisplayed: 4.7µH  [IHLP-2525CZ]  (hidden comment: IHLP2525CZER4R7M01)
NT1  Net-Tie  [Net-Tie_10milWide_30milLong]  (net tie, no BOM)
NT2  Net-Tie  [Net-Tie_10milWide_30milLong]  (net tie, no BOM)
NT3  Net-Tie  [Net-Tie_10milWide_30milLong]  (net tie, no BOM)
NT4  Net-Tie  [Net-Tie_10milWide_30milLong]  (net tie, no BOM)
Q1  SUD50P06-15L-E3  [DPAK]  (value not drawn)
Q2  Si4840BDY-T1-GE3  [SOIC-8]  (value not drawn)
Q3  Si4840BDY-T1-GE3  [SOIC-8]  (value not drawn)
Q4  IRLR3114ZTRPBF  [DPAK]
Q5  Si4840BDY-T1-GE3  [SOIC-8]  (value not drawn)
Q6  Si4840BDY-T1-GE3  [SOIC-8]  (value not drawn)
R1  ValueDisplayed: 0.022  [0612]  (hidden comment: PRL1632-R022-F-T1)
R2  ValueDisplayed: 10.0  [0603]  (hidden comment: CRCW060310R0FKEA)
R3  ValueDisplayed: 432k  [0603]  (hidden comment: CRCW0603432KFKEA)
R4  ValueDisplayed: 1.50k  [0603]  (hidden comment: ERJ-3EKF1501V)
R5  ValueDisplayed: 82.5k  [0603]  (hidden comment: CRCW060382K5FKEA)
R6  ValueDisplayed: 0.015  [4527]  (hidden comment: WSR3R0150FEA)
R7  ValueDisplayed: 49.9k  [0603]  (hidden comment: RG1608P-4992-B-T5)
R8  ValueDisplayed: 0.015  [0612]  (hidden comment: PRL1632-R015-F-T1)
R9  ValueDisplayed: 10.0  [0603]  (hidden comment: CRCW060310R0FKEA)
R10  ValueDisplayed: 255k  [0603]  (hidden comment: CRCW0603255KFKEA)
R11  ValueDisplayed: 82.5k  [0603]  (hidden comment: CRCW060382K5FKEA)
R12  ValueDisplayed: 1.0k  [0603]  (hidden comment: CRCW06031K00JNEA)
R13  ValueDisplayed: 39k  [0603]  (hidden comment: RC0603JR-0739KL)
R14  ValueDisplayed: 27.0k  [0603]  (hidden comment: RT0603DRD0727KL)
R15  ValueDisplayed: 10.0k  [0603]  (hidden comment: RC0603FR-0710KL)
U1  TPS43330AQDAPRQ1  [DAP0038B_N]

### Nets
GND: C1.2 C2.2(-) C3.2(-) C4.2 C5.2(-) C6.2(-) C7.2(-) C8.2 C9.2 C10.2 C11.2 C12.2 C13.2 C15.1 C16.1 C17.2 C19.2 C20.2 C21.2 C22.1 C23.2 C24.2 C25.2 C27.2 C32.2 C33.2 C34.2 J2.1 Q3.1(S) Q3.2(S) Q3.3(S) Q6.1(S) Q6.2(S) Q6.3(S) R5.1 R6.1 R7.1 R11.1 R13.1 R14.1 R15.1 U1.9(PGNDA) U1.20(SYNC) U1.23(AGND) U1.30(PGNDB) U1.36(DIV) U1.39(DAP)
3V3: C19.1 C20.1 C21.1 NT4.2 R8.2 R10.2 ; off-sheet 3V3
5V0: C9.1 C10.1 C16.2 NT2.2 R1.2 R3.2 U1.37(EXTSUP) ; off-sheet 5V0
COMPA: C29.1 C32.1 U1.13(COMPA) ; off-sheet COMPA
COMPB: C30.1 C33.1 U1.26(COMPB) ; off-sheet COMPB
COMPC: C31.1 C34.1 U1.18(COMPC) ; off-sheet COMPC
DS: C13.1 R4.2 U1.2(DS) ; off-sheet DS
FBA: C12.1 R3.1 R5.2 U1.12(FBA) ; off-sheet FBA
FBB: C27.1 R10.1 R11.2 U1.27(FBB) ; off-sheet FBB
GA1: Q2.4(G) U1.6(GA1) ; off-sheet GA1
GA2: Q3.4(G) U1.8(GA2) ; off-sheet GA2
GB1: Q5.4(G) U1.33(GB1) ; off-sheet GB1
GB2: Q6.4(G) U1.31(GB2) ; off-sheet GB2
GC1: Q4.1(G) U1.3(GC1) ; off-sheet GC1
GC2: Q1.1(G) U1.4(GC2) ; off-sheet GC2
PHA: C14.1 L2.1 Q2.1(S) Q2.2(S) Q2.3(S) Q3.5(D) Q3.6(D) Q3.7(D) Q3.8(D) R2.2 U1.7(PHA) ; off-sheet PHA
PHB: C26.1 L3.1 Q5.1(S) Q5.2(S) Q5.3(S) Q6.5(D) Q6.6(D) Q6.7(D) Q6.8(D) R9.2 U1.32(PHB) ; off-sheet PHB
SA1: C18.1 NT1.1 U1.10(SA1) ; off-sheet SA1
SA2: C18.2 NT2.1 U1.11(SA2) ; off-sheet SA2
SB1: C28.2 NT3.1 U1.29(SB1) ; off-sheet SB1
SB2: C28.1 NT4.1 U1.28(SB2) ; off-sheet SB2
VBAT: C2.1(+) C3.1(+) C4.1 J1.1 L1.1 R12.1 ; off-sheet VBAT
VIN: C1.1 C5.1(+) C6.1(+) C7.1(+) C8.1 C15.2 D1.3(K) Q1.3(S) Q2.5(D) Q2.6(D) Q2.7(D) Q2.8(D) Q5.5(D) Q5.6(D) Q5.7(D) Q5.8(D) U1.38(VIN) ; off-sheet VIN
VREG: C17.1 U1.19(ENC) U1.35(VREG) ; off-sheet VREG
NetC11_1: C11.1 R2.1
NetC14_2: C14.2 U1.5(CBA)
NetC22_2: C22.2 U1.21(DLYAB)
NetC23_1: C23.1 R9.1
NetC24_1: C24.1 U1.14(SSA)
NetC25_1: C25.1 U1.25(SSB)
NetC26_2: C26.2 U1.34(CBB)
NetC29_2: C29.2 R13.2
NetC30_2: C30.2 R14.2
NetC31_2: C31.2 R15.2
NetD1_1: D1.1(A) D1.2(A) D2.1(A) D2.2(A) L1.2 Q1.4(D)
NetD2_3: D2.3(K) Q4.4(D)
NetL2_2: L2.2 NT1.2 R1.1
NetL3_2: L3.2 NT3.2 R8.1
NetQ4_3: Q4.3(S) R4.1 R6.2
NetR7_2: R7.2 U1.22(RT)
NetR12_2: R12.2 U1.1(VBAT)

Not connected (* = marked no-connect by the designer): U1 15(PGA)* 16(ENA)* 17(ENB)* 24(PGB)*

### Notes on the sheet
- (4-40V)
- Input
- DNI
- (near C11) DNI
- Note: Testpoints may be removed in customers designs, based on test-requirements.

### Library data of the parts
C1 C15 = CGA9N3X7R1H106K230KB: CAP, CERM, 10 µF, 50 V, +/- 10%, X7R, 2220; Manufacturer: TDK; Polarized: N; CompType: Capacitor; Value: 10uF; U/M: EA; Cap_F: 0.00001; Tolerance_%: 10; Value1: Unknown; VDC_V: 50; Value2: 50V; TaMin_C: -55; TaMax_C: 125
C2 C3 = EEE-TK1J221AQ: CAP, AL, 220 µF, 63 V, +/- 20%, 0.26 ohm, SMD; Manufacturer: Panasonic; Polarized: Y; CompType: Capacitor; Value: 220uF; U/M: EA; Cap_F: 0.00022; Tolerance_%: 20; VDC_V: 63; Value2: 63V; ESR_ohm: 0.26; IRMS_A: 0.35; TaMin_C: -40; TaMax_C: 125; Cap_Case: 12.5x13.5
C4 C8 = CL31B105JAHNNNE: CAP, CERM, 1 µF, 25 V, +/- 5%, X7R, 1206_190; Manufacturer: Samsung Electro-Mechanics; Polarized: N; CompType: Capacitor; Value: 1uF; U/M: EA; Cap_F: 0.000001; Tolerance_%: 5; Value1: Unknown; VDC_V: 25; Value2: 25V; TaMin_C: -55; TaMax_C: 125; Cap_Case: 1206
C5-C7 = EEU-FC1H561: CAP, AL, 560 µF, 50 V, +/- 20%, 0.05 ohm, TH; Manufacturer: Panasonic; Polarized: Y; CompType: Capacitor; Value: 560uF; U/M: EA; Cap_F: 0.00056; Tolerance_%: 20; VDC_V: 50; Value2: 50V; ESR_ohm: 0.05; IRMS_A: 1.832; TaMin_C: -55; TaMax_C: 105; Cap_Case: 12.5x25mm
C9 C19 C20 = LMK325ABJ107MMHT: CAP, CERM, 100 µF, 10 V, +/- 20%, X5R, 1210; Manufacturer: Taiyo Yuden; Polarized: N; CompType: Capacitor; Value: 100uF; U/M: EA; Cap_F: 0.0001; Tolerance_%: 20; Value1: Unknown; VDC_V: 10; Value2: 10V; TaMin_C: -55; TaMax_C: 85; Cap_Case: 1210
C10 C21 = C1206C105K3RACTU: CAP, CERM, 1 µF, 25 V, +/- 10%, X7R, 1206; Manufacturer: Kemet; Polarized: N; CompType: Capacitor; Value: 1uF; U/M: EA; Cap_F: 0.000001; Tolerance_%: 10; ESR_ohm: 0.011; Value1: 0.011 ohm; VDC_V: 25; Value2: 25V; IRMS_A: 3.55; TaMin_C: -55; TaMax_C: 125
C11 = GRM1885C1E102JA01D: CAP, CERM, 1000 pF, 25 V, +/- 5%, C0G/NP0, 0603; Manufacturer: MuRata; Polarized: N; CompType: Capacitor; Value: 1000pF; U/M: EA; Cap_F: 0.000000001; Tolerance_%: 5; Value1: Unknown; VDC_V: 25; Value2: 25V; TaMin_C: -55; TaMax_C: 125
C12 C27 = GRM1885C1H470JA01D: CAP, CERM, 47 pF, 50 V, +/- 5%, C0G/NP0, 0603; Manufacturer: MuRata; Polarized: N; CompType: Capacitor; Value: 47pF; U/M: EA; Cap_F: 0.000000000047; Tolerance_%: 5; Value1: Unknown; VDC_V: 50; Value2: 50V; TaMin_C: -55; TaMax_C: 125
C13 = C0603C471K5RACTU: CAP, CERM, 470 pF, 50 V, +/- 10%, X7R, 0603; Manufacturer: Kemet; Polarized: N; CompType: Capacitor; Value: 470pF; U/M: EA; Cap_F: 0.00000000047; Tolerance_%: 10; Value1: Unknown; VDC_V: 50; Value2: 50V; TaMin_C: -55; TaMax_C: 125
C14 C26 = GRM188R61E224KA88D: CAP, CERM, 0.22 µF, 25 V, +/- 10%, X5R, 0603; Manufacturer: MuRata; Polarized: N; CompType: Capacitor; Value: 0.22uF; U/M: EA; Cap_F: 0.00000022; Tolerance_%: 10; Value1: Unknown; VDC_V: 25; Value2: 25V; TaMin_C: -55; TaMax_C: 85; Cap_Case: 0603
C16 = C0603C104J3RACTU: CAP, CERM, 0.1 µF, 25 V, +/- 5%, X7R, 0603; Manufacturer: Kemet; Polarized: N; CompType: Capacitor; Value: 0.1uF; U/M: EA; Cap_F: 0.0000001; Tolerance_%: 5; Value1: Unknown; VDC_V: 25; Value2: 25V; TaMin_C: -55; TaMax_C: 125
C17 = GRM188R61E475KE11D: CAP, CERM, 4.7 µF, 25 V, +/- 10%, X5R, 0603_095; Manufacturer: MuRata; Polarized: N; CompType: Capacitor; Value: 4.7uF; U/M: EA; Cap_F: 0.0000047; Tolerance_%: 10; Value1: Unknown; VDC_V: 25; Value2: 25V; TaMin_C: -55; TaMax_C: 85; Cap_Case: 0603
C18 C24 C25 C28 = GRM188R71E103KA01D: CAP, CERM, 0.01 µF, 25 V, +/- 10%, X7R, 0603; Manufacturer: MuRata; Polarized: N; CompType: Capacitor; Value: 0.01uF; U/M: EA; Cap_F: 0.00000001; Tolerance_%: 10; Value1: Unknown; VDC_V: 25; Value2: 25V; TaMin_C: -55; TaMax_C: 125
C22 C23 = GRM188R71H102KA01D: CAP, CERM, 1000 pF, 50 V, +/- 10%, X7R, 0603; Manufacturer: MuRata; Polarized: N; CompType: Capacitor; Value: 1000pF; U/M: EA; Cap_F: 0.000000001; Tolerance_%: 10; Value1: Unknown; VDC_V: 50; Value2: 50V; TaMin_C: -55; TaMax_C: 125
C29 = C1005C0G1E681J: CAP, CERM, 680 pF, 25 V, +/- 5%, C0G/NP0, 0402; Manufacturer: TDK; Polarized: N; CompType: Capacitor; Value: 680pF; U/M: EA; Cap_F: 0.00000000068; Tolerance_%: 5; Value1: Unknown; VDC_V: 25; Value2: 25V; TaMin_C: -55; TaMax_C: 125
C30 = C0603X102K5RACTU: CAP, CERM, 1000 pF, 50 V, +/- 10%, X7R, 0603; Manufacturer: Kemet; Polarized: N; CompType: Capacitor; Value: 1000pF; U/M: EA; Cap_F: 0.000000001; Tolerance_%: 10; Value1: Unknown; VDC_V: 50; Value2: 50V; TaMin_C: -55; TaMax_C: 125
C31 = 06033C123JAT2A: CAP, CERM, 0.012 µF, 25 V, +/- 5%, X7R, 0603; Manufacturer: AVX; Polarized: N; CompType: Capacitor; Value: 0.012uF; U/M: EA; Cap_F: 0.000000012; Tolerance_%: 5; Value1: Unknown; VDC_V: 25; Value2: 25V; TaMin_C: -55; TaMax_C: 125
C32 = C1608C0G1H180J: CAP, CERM, 18 pF, 50 V, +/- 5%, C0G/NP0, 0603; Manufacturer: TDK; Polarized: N; CompType: Capacitor; Value: 18pF; U/M: EA; Cap_F: 0.000000000018; Tolerance_%: 5; ESR_ohm: 0.4028; Value1: 0.4028 ohm; VDC_V: 50; Value2: 50V; TaMin_C: -55; TaMax_C: 125
C33 = 06035A270JAT2A: CAP, CERM, 27 pF, 50 V, +/- 5%, C0G/NP0, 0603; Manufacturer: AVX; Polarized: N; CompType: Capacitor; Value: 27pF; U/M: EA; Cap_F: 0.000000000027; Tolerance_%: 5; ESR_ohm: 0.232; Value1: 0.232 ohm; VDC_V: 50; Value2: 50V; TaMin_C: -55; TaMax_C: 125
C34 = GRM1885C1H121JA01D: CAP, CERM, 120 pF, 50 V, +/- 5%, C0G/NP0, 0603; Manufacturer: MuRata; Polarized: N; CompType: Capacitor; Value: 120pF; U/M: EA; Cap_F: 0.00000000012; Tolerance_%: 5; Value1: Unknown; VDC_V: 50; Value2: 50V; TaMin_C: -55; TaMax_C: 125
D1 D2 = PMEG045V150EPDAZ: Diode, Schottky, 45 V, 15 A, CFP15; Manufacturer: NXP Semiconductor; U/M: EA; Vf_V: 0.49; Value: 45V; Value1: 15A; Value2: 0.49V; Io_A: 15; Vr_V: 45; TJmax_C: 175
J1 = SPC15363: BANANA JACK, SOLDER LUG, RED, TH; Manufacturer: Tenma; SymbolCreator: a0412235; U/M: EA
J2 = SPC15354: BANANA JACK, SOLDER LUG, BLACK, TH; Manufacturer: Tenma; SymbolCreator: a0412235; U/M: EA
L1 = 744325180: Inductor, Shielded Drum Core, Superflux, 1.8uH, 16A, 0.0035 ohm, SMD; Manufacturer: Wurth Elektronik eiSos; Ind_H: 1.8E-6; Imax_A: 16; Irms: 16A @ 50C rise; Isat: 18A @ 30% inductance drop; DCR_ohm: 0.0035; U/M: EA
L2 = IHLP2525CZER100M01: Inductor, Shielded Drum Core, Powdered Iron, 10uH, 3A, 0.102 ohm, SMD; Manufacturer: Vishay-Dale; Ind_H: 10.0E-6; Imax_A: 3; Irms: 3A @ 40C rise; Isat: 7A @ 20% inductance drop; DCR_ohm: 0.102; U/M: EA
L3 = IHLP2525CZER4R7M01: Inductor, Shielded Drum Core, Powdered Iron, 4.7uH, 5.5A, 0.037 ohm, SMD; Manufacturer: Vishay-Dale; Ind_H: 4.7E-6; Imax_A: 5.5; Irms: 5.5A @ 40C rise; Isat: 10A @ 20% inductance drop; DCR_ohm: 0.037; U/M: EA
NT1-NT4 = Net-Tie: Single point connection between nets.; SymbolCreator: codlsc
Q1 = SUD50P06-15L-E3: MOSFET, P-CH, -60 V, -50 A, DPAK; Manufacturer: Vishay-Semiconductor; Alternate Manufacturer: None; U/M: EA; ChType: P; Value: -60V; Value1: 0.015 ohm; Rdson45_ohm: 0.015; Value2: 165 nC; QgTyp_nC: 165; Vgs_V: -3
Q2 Q3 Q5 Q6 = Si4840BDY-T1-GE3: MOSFET, N-CH, 40 V, 19 A, SOIC-8; Manufacturer: Vishay-Siliconix; Alternate Manufacturer: None; Value: 40V; U/M: EA; ChType: N; VdsMax_V: 40; Value1: 0.012 ohm; Rdson45_ohm: 0.012; Value2: 15 nC; QgTyp_nC: 15; Vgs_V: 20; IdsMax_A: 19; AEC Category: Q101
Q4 = IRLR3114ZTRPBF: MOSFET, N-CH, 40 V, 42 A, DPAK; Manufacturer: International Rectifier; Alternate Manufacturer: None; U/M: EA; ChType: N; Value: 40V; VdsMax_V: 40; Value1: 0.0065 ohm; Rdson45_ohm: 0.0065; Value2: 40 nC; Vgs_V: 16; IdsMax_A: 42
R1 = PRL1632-R022-F-T1: RES, 0.022, 1%, 1 W, 0612; Manufacturer: Susumu Co Ltd; CompType: Resistor; Value: 0.022; Value_Code: R022; Tolerance_%: 1; Value2: 1W; TempCo: 100 ppm/C; EIA_Code: E96; U/M: EA
R2 R9 = CRCW060310R0FKEA: RES, 10.0, 1%, 0.1 W, 0603; Manufacturer: Vishay-Dale; CompType: Resistor; Value: 10.0; Res_ohm: 10; Value_Code: 10R0; Tolerance_%: 1; Power_W: 0.1; Value2: 0.1W; VDC_V: 75; TempCo: 100 ppm/C; EIA_Code: E96; U/M: EA
R3 = CRCW0603432KFKEA: RES, 432 k, 1%, 0.1 W, 0603; Manufacturer: Vishay-Dale; CompType: Resistor; Value: 432k; Res_ohm: 432000; Tolerance_%: 1; Power_W: 0.1; Value2: 0.1W; VDC_V: 75; TempCo: 100 ppm/C; EIA_Code: E96; U/M: EA
R4 = ERJ-3EKF1501V: RES, 1.50 k, 1%, 0.1 W, 0603; Manufacturer: Panasonic; CompType: Resistor; Value: 1.50k; Res_ohm: 1500; Value_Code: 1k50; Tolerance_%: 1; Power_W: 0.1; Value2: 0.1W; VDC_V: 75; TempCo: 100 ppm/C; EIA_Code: E96; U/M: EA
R5 R11 = CRCW060382K5FKEA: RES, 82.5 k, 1%, 0.1 W, 0603; Manufacturer: Vishay-Dale; CompType: Resistor; Value: 82.5k; Res_ohm: 82500; Value_Code: 82k5; Tolerance_%: 1; Power_W: 0.1; Value2: 0.1W; VDC_V: 75; TempCo: 100 ppm/C; EIA_Code: E96; U/M: EA
R6 = WSR3R0150FEA: RES, 0.015, 1%, 3 W, 4527; Manufacturer: Vishay-Dale; CompType: Resistor; Value: 0.015; Value_Code: R015; Tolerance_%: 1; Power_W: 3; Value2: 3W; TempCo: 75 ppm/C; EIA_Code: E96; U/M: EA; AEC Category: Q200
R7 = RG1608P-4992-B-T5: RES, 49.9 k, 0.1%, 0.1 W, 0603; Manufacturer: Susumu Co Ltd; CompType: Resistor; Value: 49.9k; Res_ohm: 49900; Value_Code: 49k9; Tolerance_%: 0.1; Value2: 0.1W; VDC_V: 75; TempCo: 25 ppm/C; EIA_Code: E192; U/M: EA; AEC Category: Q200
R8 = PRL1632-R015-F-T1: RES, 0.015, 1%, 1 W, 0612; Manufacturer: Susumu Co Ltd; CompType: Resistor; Value: 0.015; Value_Code: R015; Tolerance_%: 1; Value2: 1W; TempCo: 200 ppm/C; EIA_Code: E96; U/M: EA
R10 = CRCW0603255KFKEA: RES, 255 k, 1%, 0.1 W, 0603; Manufacturer: Vishay-Dale; CompType: Resistor; Value: 255k; Res_ohm: 255000; Tolerance_%: 1; Power_W: 0.1; Value2: 0.1W; VDC_V: 75; TempCo: 100 ppm/C; EIA_Code: E96; U/M: EA; AEC Category: Q200
R12 = CRCW06031K00JNEA: RES, 1.0 k, 5%, 0.1 W, 0603; Manufacturer: Vishay-Dale; CompType: Resistor; Value: 1.0k; Res_ohm: 1000; Value_Code: 1k00; Tolerance_%: 5; Power_W: 0.1; Value2: 0.1W; VDC_V: 75; TempCo: 200 ppm/C; EIA_Code: E24; U/M: EA
R13 = RC0603JR-0739KL: RES, 39 k, 5%, 0.1 W, 0603; Manufacturer: Yageo America; CompType: Resistor; Value: 39k; Res_ohm: 39000; Value_Code: 39k0; Tolerance_%: 5; Power_W: 0.1; Value2: 0.1W; VDC_V: 50; TempCo: 100 ppm/C; EIA_Code: E24; U/M: EA
R14 = RT0603DRD0727KL: RES, 27.0 k, 0.5%, 0.1 W, 0603; Manufacturer: Yageo America; CompType: Resistor; Value: 27.0k; Res_ohm: 27000; Value_Code: 27k0; Tolerance_%: 0.5; Power_W: 0.1; Value2: 0.1W; VDC_V: 75; TempCo: 25 ppm/C; U/M: EA; AEC Category: Q200
R15 = RC0603FR-0710KL: as R20 on sheet TIDA-00801A_O9039A360
U1 = TPS43330AQDAPRQ1: LOW IQ, SINGLE BOOST, DUAL SYNCHRONOUS BUCK CONTROLLER, DAP0038B; Manufacturer: Texas Instruments; SymbolCreator: a0411947; CompType: IC; U/M: EA

## Sheet TIDA-00801A_TPS51200.schdoc: TPS51200
size 431 x 279 mm; Date: Not shown in title block; ApprovedBy: Not shown in title block; CheckedBy: Not shown in title block; Author: Not shown in title block; CompanyName: Not shown in title block; Engineer: Not shown in title block; Organization: Not shown in title block; Address1: Not shown in title block; Address2: Not shown in title block; Address3: Not shown in title block; Address4: Not shown in title block; DocumentNumber: 1; Revision: Use project parameter SCH_Rev; SheetNumber: 3; SheetTotal: 6; PageSetup: Record=PageOptions¦CenterHorizontal=True¦CenterVertical=True¦PrintScale=1.00¦XCorrection=1.00¦YCorrection=1.00¦PrintKind=0¦BorderSize=5000000¦LeftOffset=0¦BottomOffset=0¦Orientation=2¦PaperLength=1000¦PaperWidth=1000¦Scale=100¦PaperSource=15¦PrintQuality=600¦MediaType=1¦DitherType=10¦PaperKind=Letter¦PrintScaleMode=1
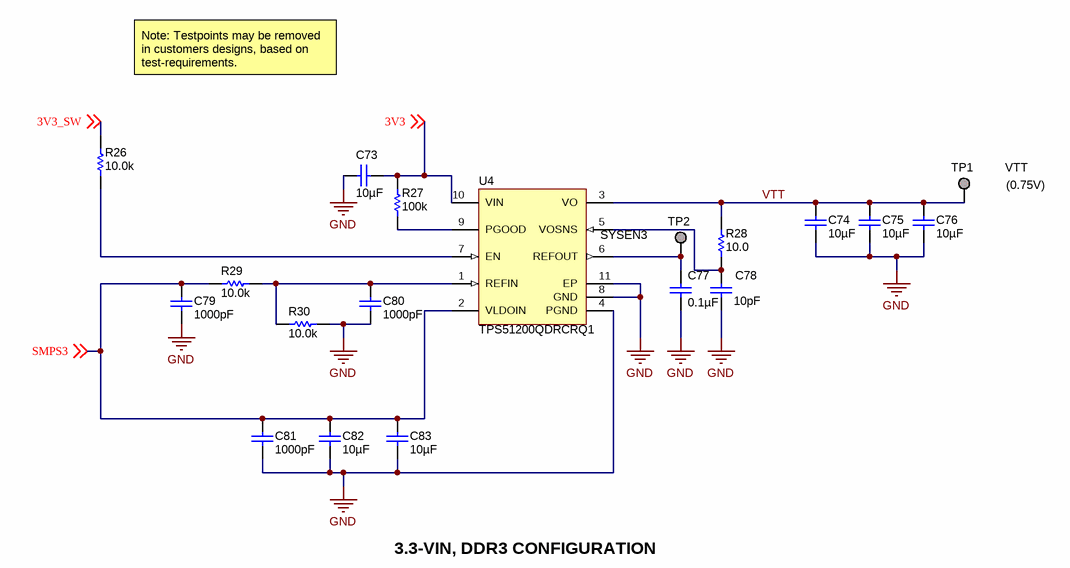
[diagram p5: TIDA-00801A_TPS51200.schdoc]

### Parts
C73  ValueDisplayed: 10µF  [0805_HV]  (hidden comment: C2012X5R1E106K125AB)
C74  ValueDisplayed: 10µF  [0805_HV]  (hidden comment: GRM21BR70J106KE76L)
C75  ValueDisplayed: 10µF  [0805_HV]  (hidden comment: GRM21BR70J106KE76L)
C76  ValueDisplayed: 10µF  [0805_HV]  (hidden comment: GRM21BR70J106KE76L)
C77  ValueDisplayed: 0.1µF  [0603]  (hidden comment: CGA3E2X8R1E104K080AA)
C78  ValueDisplayed: 10pF  [0603]  (hidden comment: GRM1885C2A100JA01D)
C79  ValueDisplayed: 1000pF  [0603]  (hidden comment: GRM1885C1H102FA01J)
C80  ValueDisplayed: 1000pF  [0603]  (hidden comment: GRM1885C1H102FA01J)
C81  ValueDisplayed: 1000pF  [0603]  (hidden comment: GRM1885C1H102FA01J)
C82  ValueDisplayed: 10µF  [0805_HV]  (hidden comment: GRM21BR70J106KE76L)
C83  ValueDisplayed: 10µF  [0805_HV]  (hidden comment: GRM21BR70J106KE76L)
R26  ValueDisplayed: 10.0k  [0603]  (hidden comment: CRCW060310K0FKEA)
R27  ValueDisplayed: 100k  [0603]  (hidden comment: CRCW0603100KJNEA)
R28  ValueDisplayed: 10.0  [0603]  (hidden comment: TNPW060310R0BEEA)
R29  ValueDisplayed: 10.0k  [0603]  (hidden comment: CRCW060310K0FKEA)
R30  ValueDisplayed: 10.0k  [0603]  (hidden comment: CRCW060310K0FKEA)
TP1  VTT  [Mill-Max_2505-2]
TP2  SYSEN3  [TP_H045P075]  (no BOM)
U4  TPS51200QDRCRQ1  [DRC0010A]

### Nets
GND: C73.2 C74.1 C75.2 C76.2 C77.2 C78.2 C79.1 C80.1 C81.1 C82.2 C83.2 R30.2 U4.4(PGND) U4.8(GND) U4.11(EP)
3V3: C73.1 R27.2 U4.10(VIN) ; off-sheet 3V3
3V3_SW: R26.2 ; off-sheet 3V3_SW
SMPS3: C79.2 C81.2 C82.1 C83.1 R29.1 U4.2(VLDOIN) ; off-sheet SMPS3
VTT: C74.2 C75.1 C76.1 R28.2 TP1.1 U4.3(VO)
NetC77_1: C77.1 TP2.1 U4.6(REFOUT)
NetC78_1: C78.1 R28.1 U4.5(VOSNS)
NetC80_2: C80.2 R29.2 R30.1 U4.1(REFIN)
NetR26_1: R26.1 U4.7(EN)
NetR27_1: R27.1 U4.9(PGOOD)

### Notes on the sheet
- Note: Testpoints may be removed in customers designs, based on test-requirements.
- (near TP1) (0.75V)
- 3.3-VIN, DDR3 CONFIGURATION

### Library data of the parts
C73 = C2012X5R1E106K125AB: CAP, CERM, 10 µF, 25 V, +/- 10%, X5R, 0805; Manufacturer: TDK; Polarized: N; CompType: Capacitor; Value: 10uF; U/M: EA; Cap_F: 0.00001; Tolerance_%: 10; Value1: Unknown; VDC_V: 25; Value2: 25V; TaMin_C: -55; TaMax_C: 85; Cap_Case: 0805
C74-C76 C82 C83 = GRM21BR70J106KE76L: CAP, CERM, 10 µF, 6.3 V, +/- 10%, X7R, 0805; Manufacturer: MuRata; Polarized: N; CompType: Capacitor; Value: 10uF; U/M: EA; Cap_F: 0.00001; Tolerance_%: 10; Value1: Unknown; VDC_V: 6.3; Value2: 6.3V; TaMin_C: -55; TaMax_C: 125; Cap_Case: 0805
C77 = CGA3E2X8R1E104K080AA: CAP, CERM, 0.1 µF, 25 V, +/- 10%, X8R, 0603; Manufacturer: TDK; Polarized: N; CompType: Capacitor; Value: 0.1uF; U/M: EA; Cap_F: 0.0000001; Tolerance_%: 10; Value1: Unknown; VDC_V: 25; Value2: 25V; TaMin_C: -55; TaMax_C: 150
C78 = GRM1885C2A100JA01D: CAP, CERM, 10 pF, 100 V, +/- 5%, C0G/NP0, 0603; Manufacturer: MuRata; Polarized: N; CompType: Capacitor; Value: 10pF; U/M: EA; Cap_F: 0.00000000001; Tolerance_%: 5; Value1: Unknown; VDC_V: 100; Value2: 100V; TaMin_C: -55; TaMax_C: 125
C79-C81 = GRM1885C1H102FA01J: CAP, CERM, 1000 pF, 50 V, +/- 1%, C0G/NP0, 0603; Manufacturer: MuRata; Polarized: N; CompType: Capacitor; Value: 1000pF; U/M: EA; Cap_F: 0.000000001; Tolerance_%: 1; Value1: Unknown; VDC_V: 50; Value2: 50V; TaMin_C: -55; TaMax_C: 125
R26 R29 R30 = CRCW060310K0FKEA: RES, 10.0 k, 1%, 0.1 W, 0603; Manufacturer: Vishay-Dale; CompType: Resistor; Value: 10.0k; Res_ohm: 10000; Value_Code: 10k0; Tolerance_%: 1; Power_W: 0.1; Value2: 0.1W; VDC_V: 75; TempCo: 100 ppm/C; EIA_Code: E96; U/M: EA
R27 = CRCW0603100KJNEA: RES, 100 k, 5%, 0.1 W, 0603; Manufacturer: Vishay-Dale; CompType: Resistor; Value: 100k; Res_ohm: 100000; Tolerance_%: 5; Power_W: 0.1; Value2: 0.1W; VDC_V: 75; TempCo: 200 ppm/C; EIA_Code: E24; U/M: EA
R28 = TNPW060310R0BEEA: RES, 10.0, 0.1%, 0.1 W, 0603; Manufacturer: Vishay-Dale; CompType: Resistor; Value: 10.0; Res_ohm: 10; Value_Code: 10R0; Tolerance_%: 0.1; Value2: 0.1W; VDC_V: 75; TempCo: 25 ppm/C; EIA_Code: E192; U/M: EA
TP1 = 2505-2-00-44-00-00-07-0: as TP16 on sheet TIDA-00801A_O9039A360
TP2 = TP_H0.45P0.75: as TP7 on sheet TIDA-00801A_O9039A360
U4 = TPS51200QDRCRQ1: Single Output Automotive LDO, 3 A, 2.3 to 3.5 V Input, with DDR Termination, 10-pin SON (DRC), -40 to 125 degC, Green (RoHS & no Sb/Br); Manufacturer: Texas Instruments; Alternate Manufacturer: None; Alternate PartNumber: Equivalent; Iout(Max)(A): 3; Iq(Typ)(mA): 0.5; Power Good: TRUE; SubFamily: Single Channel LDO; Vin(Max)(V): 3.5; Vin(Min)(V): 2.3

## Sheet TIDA-00801A_Hardware.SchDoc: Hardware
size 431 x 279 mm; Date: Not shown in title block; ApprovedBy: Not shown in title block; CheckedBy: Not shown in title block; Author: Not shown in title block; CompanyName: Not shown in title block; Engineer: Not shown in title block; Organization: Not shown in title block; Address1: Not shown in title block; Address2: Not shown in title block; Address3: Not shown in title block; Address4: Not shown in title block; DocumentNumber: 1; Revision: Use project parameter SCH_Rev; SheetNumber: 6; SheetTotal: 6; PageSetup: Record=PageOptions¦CenterHorizontal=True¦CenterVertical=True¦PrintScale=1.00¦XCorrection=1.00¦YCorrection=1.00¦PrintKind=0¦BorderSize=5000000¦LeftOffset=0¦BottomOffset=0¦Orientation=2¦PaperLength=1000¦PaperWidth=1000¦Scale=100¦PaperSource=15¦PrintQuality=600¦MediaType=1¦DitherType=10¦PaperKind=Letter¦PrintScaleMode=1
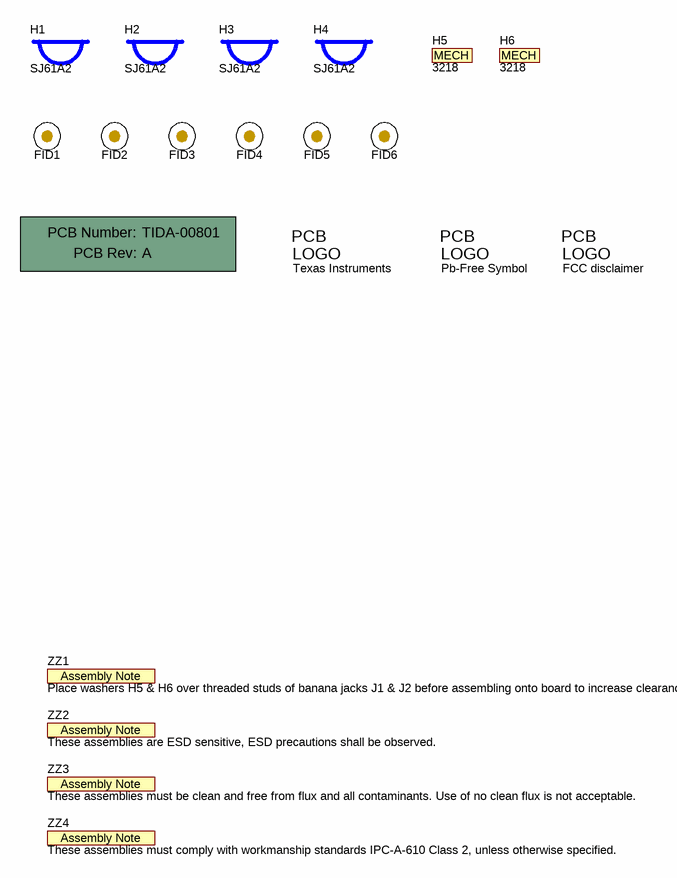
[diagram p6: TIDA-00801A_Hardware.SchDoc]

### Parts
!PCB1  Printed Circuit Board  (value not drawn)  (mechanical)
FID1  Fiducial  [Fiducial10-20]  (value not drawn)
FID2  Fiducial  [Fiducial10-20]  (value not drawn)
FID3  Fiducial  [Fiducial10-20]  (value not drawn)
FID4  Fiducial  [Fiducial10-20]  (value not drawn)
FID5  Fiducial  [Fiducial10-20]  (value not drawn)
FID6  Fiducial  [Fiducial10-20]  (value not drawn)
H1  SJ61A2  [Bumpon_SJ61A2]
H2  SJ61A2  [Bumpon_SJ61A2]
H3  SJ61A2  [Bumpon_SJ61A2]
H4  SJ61A2  [Bumpon_SJ61A2]
H5  3218  (mechanical)
H6  3218  (mechanical)
Logo1  Texas Instruments  [TI_Stacked_SolderMask_Small]  (no BOM)
Logo2  Pb-Free Symbol  [Pb-Free_Overlay_Small]  (no BOM)
Logo3  FCC disclaimer  [FCC_disclaimer]  (no BOM)
ZZ1  Place washers H5 & H6 over threaded studs of banana jacks J1 & J2 before assembling onto board to increase clearance below them.  [AssemblyNote]  (no BOM)
ZZ2  These assemblies are ESD sensitive, ESD precautions shall be observed.  [AssemblyNote]  (no BOM)
ZZ3  These assemblies must be clean and free from flux and all contaminants. Use of no clean flux is not acceptable.  [AssemblyNote]  (no BOM)
ZZ4  These assemblies must comply with workmanship standards IPC-A-610 Class 2, unless otherwise specified.  [AssemblyNote]  (no BOM)

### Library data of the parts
!PCB1 = PCB: Manufacturer: Any; PartNumber: TIDA-00801; SymbolCreator: a0412235
FID1-FID6 = Fiducial: Fiducial mark.  There is nothing to buy or mount.; SymbolCreator: codlsc
H1-H4 = SJ61A2: Bumpon, Hemisphere, 0.375 X 0.235, Black; Manufacturer: 3M; SymbolCreator: a0412235
H5 H6 = MechPart: WASHER FLAT 1/4 NYLON; Manufacturer: Keystone; SymbolCreator: codlsc; CompType: Mechanical; U/M: EA
Logo1 = TI_Logo: Texas Instrument Corporate Signature; SymbolCreator: codlsc
Logo2 = Pb-Free: SymbolCreator: a0412235
Logo3 = FCC_disclaimer: SymbolCreator: codlsc
ZZ1-ZZ4 = AssemblyNote: SymbolCreator: codlsc

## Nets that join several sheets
GND: TIDA-00801A_O9039A360 (108 pins), TIDA-00801A_TPS22965 (6 pins), TIDA-00801A_TPS43330 (47 pins), TIDA-00801A_TPS51200 (15 pins)
3V3: TIDA-00801A_O9039A360 (47 pins), TIDA-00801A_TPS22965 (C70.1 TP3.1 U3.1 U3.2), TIDA-00801A_TPS43330 (6 pins), TIDA-00801A_TPS51200 (C73.1 R27.2 U4.10)
3V3_SW: TIDA-00801A_O9039A360 (6 pins), TIDA-00801A_TPS22965 (C69.1 TP5.1 U3.7 U3.8), TIDA-00801A_TPS51200 (R26.2)
5V0: TIDA-00801A_O9039A360 (5 pins), TIDA-00801A_TPS22965 (C72.1 TP4.1 U3.4), TIDA-00801A_TPS43330 (7 pins)
REGEN1: TIDA-00801A_O9039A360 (U2.F8), TIDA-00801A_TPS22965 (U3.3)
SMPS3: TIDA-00801A_O9039A360 (C48.1 L6.2 TP17.1 U2.K13), TIDA-00801A_TPS51200 (6 pins)

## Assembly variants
001: not fitted C2 C5 C11 C23 FID1 FID2 FID3 FID4 FID5 FID6 R2 R9 R21 R22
